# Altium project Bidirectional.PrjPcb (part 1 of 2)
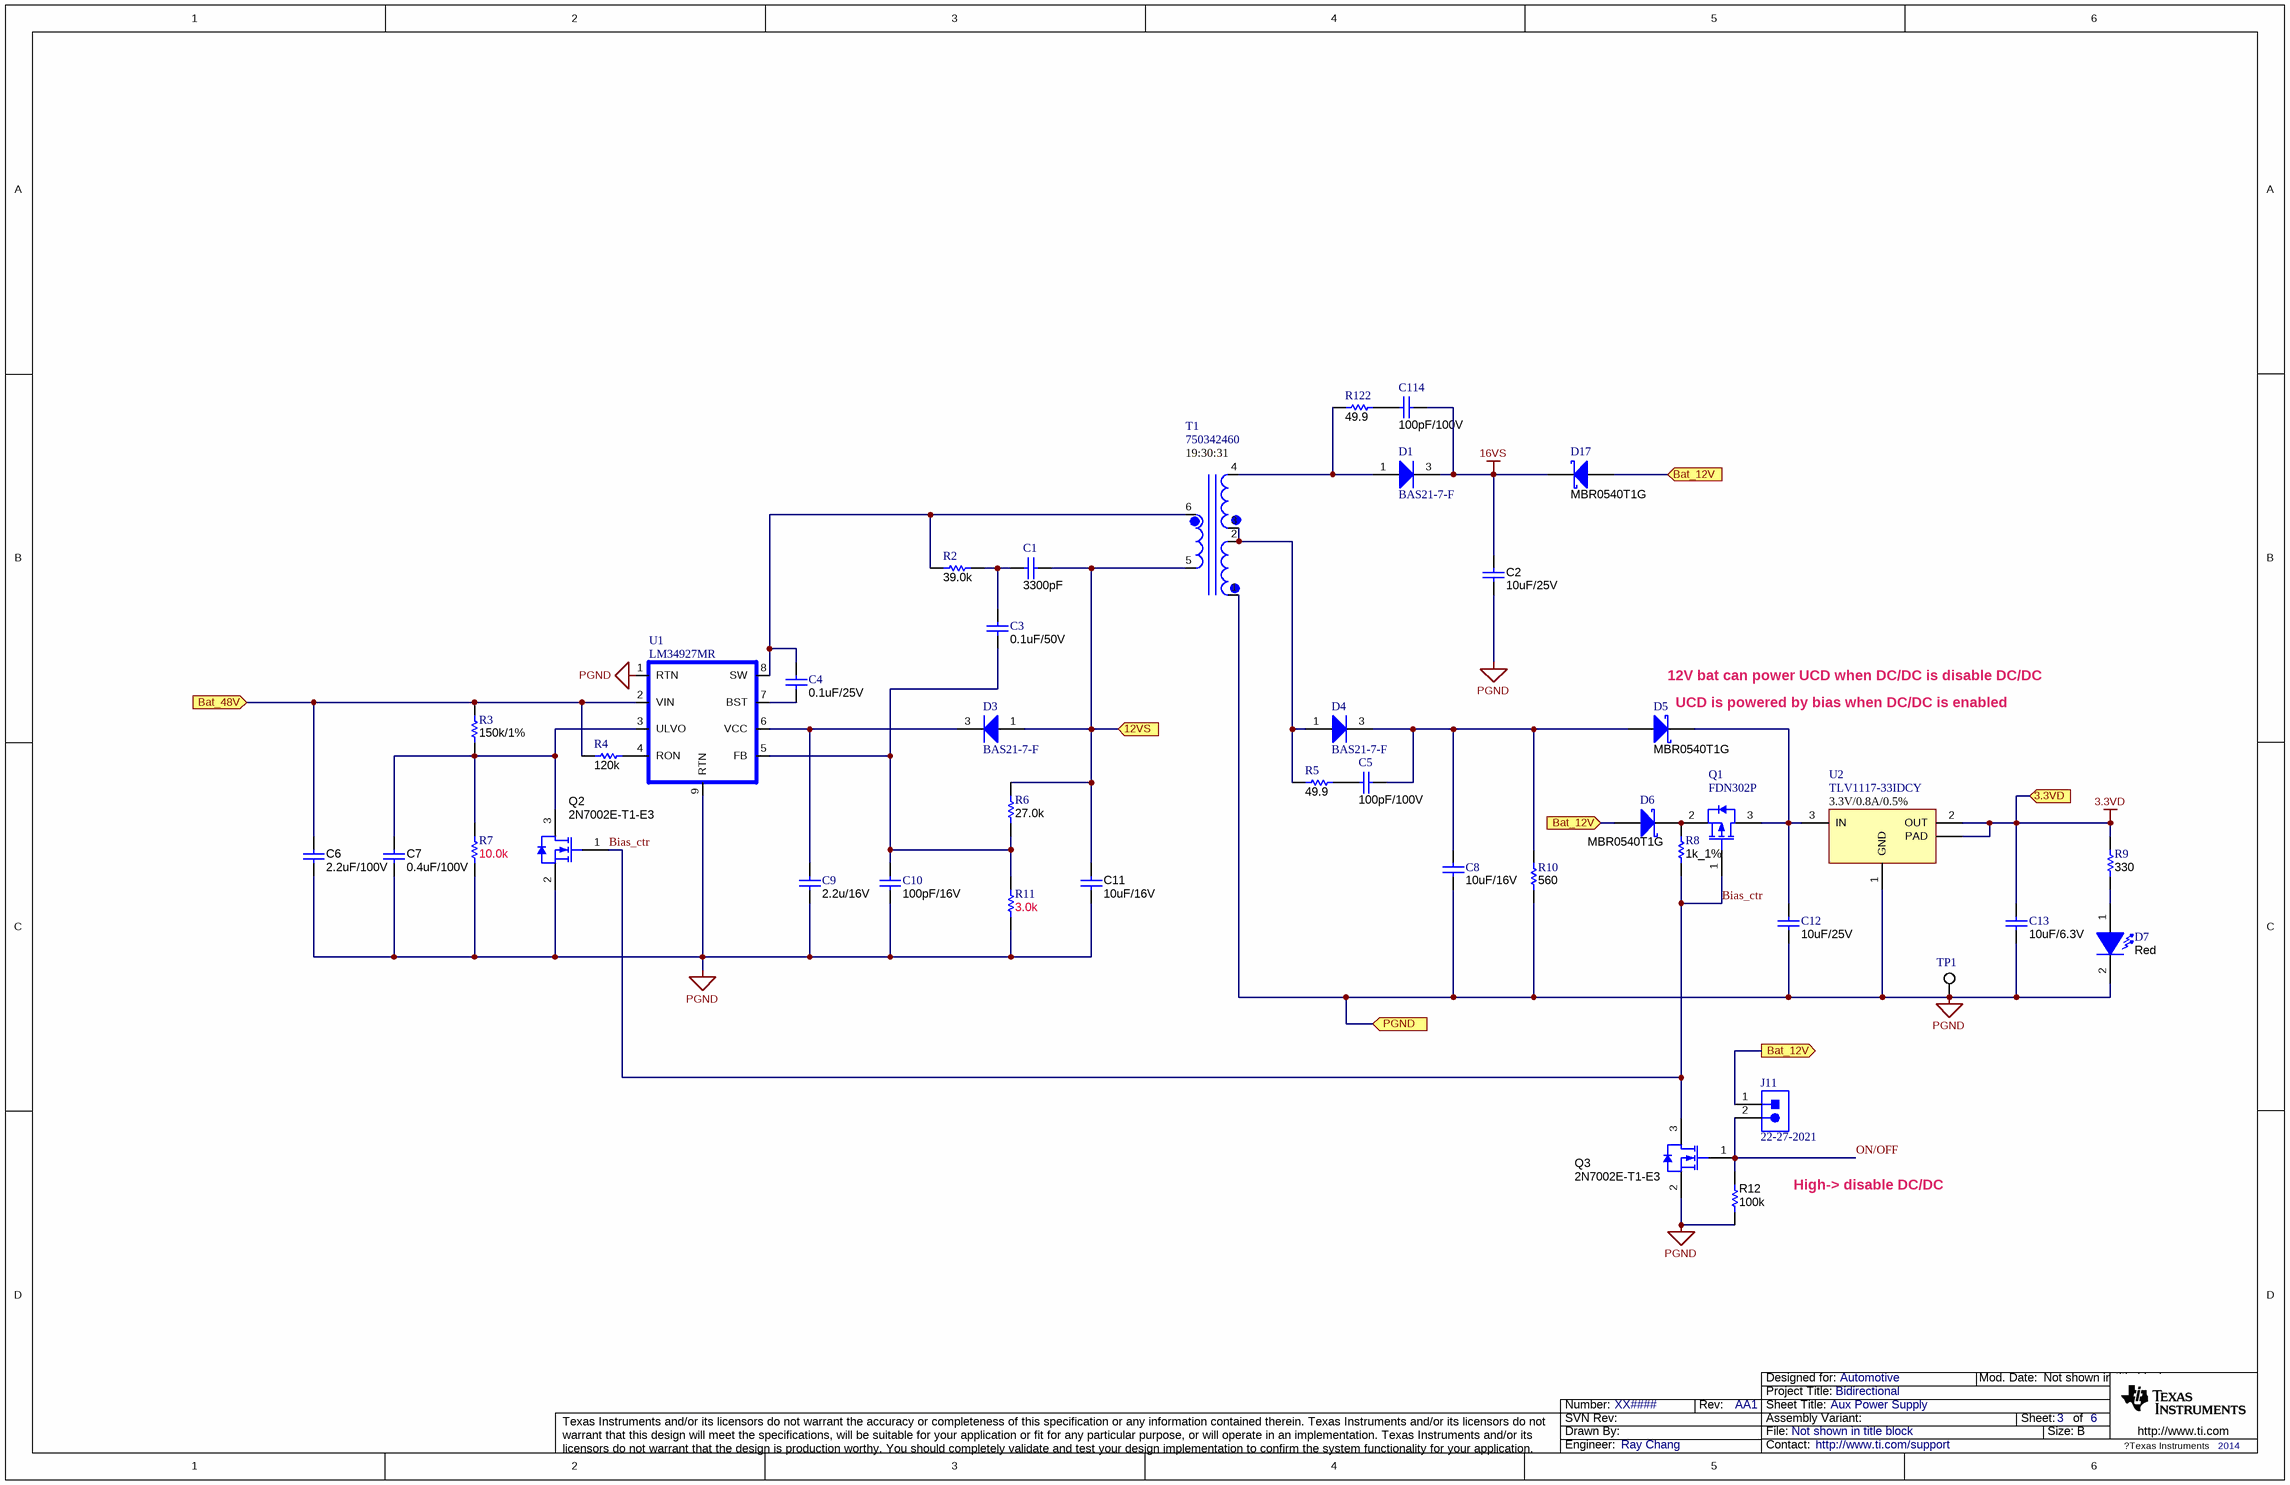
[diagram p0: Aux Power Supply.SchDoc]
CopyrightYear: 2014; PCB_Layout: Ray Chang; PCB_Rev: E1; PRJ_Customer: Automotive; PRJ_Engineer: Ray Chang; PRJ_Number: XX####; PRJ_Title: Bidirectional; SCH_Rev: AA1; TechSupport: http://www.ti.com/support
6 sheets, 417 parts. Net scope: flat (ports and power ports of the same name join across sheets).
Board file: bidirectional.PcbDoc
Sheets:
  Aux Power Supply.SchDoc
  bidirectional-MCU.SchDoc
  bidirectional-phase1.SchDoc
  bidirectional-Phase2&3.SchDoc
  bidirectional-Phase4.SchDoc
  Hardware_ANSI-B.SchDoc

## Sheet Aux Power Supply.SchDoc: Aux Power Supply
size 431 x 279 mm; Date: Not shown in title block; ApprovedBy: Not shown in title block; CheckedBy: Not shown in title block; Author: Not shown in title block; CompanyName: Not shown in title block; Engineer: Not shown in title block; Organization: Not shown in title block; Address1: Not shown in title block; Address2: Not shown in title block; Address3: Not shown in title block; Address4: Not shown in title block; DocumentNumber: 3; Revision: Use project parameter SCH_Rev; SheetNumber: 3; SheetTotal: 6; PageSetup: Record=PageOptions|CenterHorizontal=True|CenterVertical=True|PrintScale=0.96|XCorrection=1.00|YCorrection=1.00|PrintKind=0|BorderSize=5000000|LeftOffset=0|BottomOffset=0|Orientation=2|PaperLength=1000|PaperWidth=1000|Scale=100|PaperSource=15|PrintQuality=600|MediaType=1|DitherType=10|PaperKind=11x17|PrintScaleMode=1

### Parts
C1  ValueDisplayed: 3300pF  [0603]  (hidden comment: 06031C332JAT2A)
C2  ValueDisplayed: 10uF/25V  [0805_HV]  (hidden comment: 0805YD106MAT2A)
C3  ValueDisplayed: 0.1uF/50V  [0603]  (hidden comment: 06035C104KAT2A)
C4  ValueDisplayed: 0.1uF/25V  [0603]  (hidden comment: 06033C104JAT2A)
C5  ValueDisplayed: 100pF/100V  [0603]  (hidden comment: C0603C101J5GAC)
C6  ValueDisplayed: 2.2uF/100V  [1206_190]  (hidden comment: GRM31CR72A225KA73L)
C7  ValueDisplayed: 0.4uF/100V  [1206]  (hidden comment: C3216X7R2A474K)
C8  ValueDisplayed: 10uF/16V  [0805_HV]  (hidden comment: 0805YD106MAT2A)
C9  ValueDisplayed: 2.2u/16V  [0805_HV]  (hidden comment: 0805YD225KAT2A)
C10  ValueDisplayed: 100pF/16V  [0603]  (hidden comment: 06035A101JAT2A)
C11  ValueDisplayed: 10uF/16V  [0805_HV]  (hidden comment: 0805YD106MAT2A)
C12  ValueDisplayed: 10uF/25V  [0805_HV]  (hidden comment: C2012X5R1E106K125AB)
C13  ValueDisplayed: 10uF/6.3V  [0603]  (hidden comment: C0603C106M9PACTU)
C114  ValueDisplayed: 100pF/100V  [0603]  (hidden comment: C0603C101J5GAC)
D1  BAS21-7-F  [SOT-23]
D3  BAS21-7-F  [SOT-23]
D4  BAS21-7-F  [SOT-23]
D5  MBR0540T1G  [SOD-123]
D6  MBR0540T1G  [SOD-123]
D7  value Red  [LED_LTST-C170]  (hidden comment: LTST-C170KRKT)
D17  MBR0540T1G  [SOD-123]
J11  22-27-2021  [MOLEX_22-27-2021]
Q1  FDN302P  [SOT-23]
Q2  2N7002E-T1-E3  [SOT-23]
Q3  2N7002E-T1-E3  [SOT-23]
R2  value 39.0k  [0603]  (hidden comment: RC0603FR-0739KL)
R3  value 150k/1%  [0603]  (hidden comment: CRCW0603150KFKEA)
R4  value 120k  [0603]  (hidden comment: RC0603FR-07120KL)
R5  value 49.9  [0603]  (hidden comment: CRCW060349R9FKEA)
R6  value 27.0k  [0603]  (hidden comment: RC0603FR-0727KL)
R7  value 10.0k  [0603]  (hidden comment: CRCW060310K0FKEA)
R8  value 1k_1%  [0603]  (hidden comment: CRCW06031K00JNEA)
R9  ValueDisplayed: 330  [0603]  (hidden comment: CRCW0603330RJNEA)
R10  value 560  [0603]  (hidden comment: RC0603FR-07560RL)
R11  value 3.0k  [0603]  (hidden comment: CRCW06033K00JNEA)
R12  ValueDisplayed: 100k  [0603]  (hidden comment: CRCW0603100KJNEA)
R122  value 49.9  [0603]  (hidden comment: CRCW060349R9FKEA)
T1  750342460  [XFMR_12X12.5-8P]
TP1  5002  [Keystone5002]  (value not drawn)
U1  LM34927MR  [DDA0008B_M]
U2  TLV1117-33IDCY  [DCY0003A_N]

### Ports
3.3VD, 12VS, Bat_12V, Bat_48V, PGND

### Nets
3.3VD: C13.1 R9.2 U2.2(OUT) U2.4(PAD) ; port 3.3VD
16VS: C2.1 C114.1 D1.3(K) D17.1(K)
PGND: C2.2 C6.2 C7.2 C8.2 C9.2 C10.2 C11.2 C12.2 C13.2 D7.2(K) Q2.2(S) Q3.2(S) R7.1 R10.1 R11.1 R12.1 T1.1 TP1.1 U1.1(RTN) U1.9(RTN) U2.1(GND) ; port PGND
12VS: C1.1 C11.1 D3.1(A) R6.2 T1.5 ; port 12VS
Bat_12V: D6.2(A) D17.2(A) J11.1 ; port Bat_12V
Bat_48V: C6.1 R3.2 R4.1 U1.2(VIN) ; port Bat_48V
Bias_ctr: Q1.1(G) Q2.1(G) Q3.3(D) R8.1
ON/OFF: J11.2 Q3.1(G) R12.2
NetC1_2: C1.2 C3.1 R2.2
NetC3_2: C3.2 C10.1 R6.1 R11.2 U1.5(FB)
NetC4_1: C4.1 R2.1 T1.6 U1.8(SW)
NetC4_2: C4.2 U1.7(BST)
NetC5_1: C5.1 C8.1 D4.3(K) D5.2(A) R10.2
NetC5_2: C5.2 R5.2
NetC7_1: C7.1 Q2.3(D) R3.1 R7.2 U1.3(ULVO)
NetC9_1: C9.1 D3.3(K) U1.6(VCC)
NetC12_1: C12.1 D5.1(K) Q1.3(D) U2.3(IN)
NetC114_2: C114.2 R122.2
NetD1_1: D1.1(A) R122.1 T1.4
NetD4_1: D4.1(A) R5.1 T1.2 T1.3
NetD6_1: D6.1(K) Q1.2(S) R8.2
NetD7_1: D7.1(A) R9.1
NetR4_2: R4.2 U1.4(RON)

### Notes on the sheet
- (near T1) 19:30:31
- (near D5) UCD is powered by bias when DC/DC is enabled
- (near D5) 12V bat can power UCD when DC/DC is disable DC/DC
- (near U2) 3.3V/0.8A/0.5%
- High-> disable DC/DC

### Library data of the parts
C1 = 06031C332JAT2A: CAP, CERM, 3300pF, 100V, +/-5%, X7R, 0603; Manufacturer: AVX; Polarized: N; CompType: Capacitor; U/M: EA; Cap_F: 0.0000000033; Tolerance_%: 5; ESR_Ohm: 0.159; Value1: 0.159 ohm; VDC_V: 100; TaMin_C: -55; TaMax_C: 125
C2 C8 C11 = 0805YD106MAT2A: CAP, CERM, 10uF, 16V, +/-20%, X5R, 0805; Manufacturer: AVX; Polarized: N; CompType: Capacitor; U/M: EA; Cap_F: 0.00001; Tolerance_%: 20; Value1: Unknown; VDC_V: 16; TaMin_C: -55; TaMax_C: 85; Cap_Case: 0805
C3 = 06035C104KAT2A: CAP, CERM, 0.1uF, 50V, +/-10%, X7R, 0603; Manufacturer: AVX; Polarized: N; CompType: Capacitor; U/M: EA; Cap_F: 0.0000001; Tolerance_%: 10; Value1: Unknown; VDC_V: 50; TaMin_C: -55; TaMax_C: 125
C4 = 06033C104JAT2A: CAP, CERM, 0.1uF, 25V, +/-5%, X7R, 0603; Manufacturer: AVX; Polarized: N; CompType: Capacitor; U/M: EA; Cap_F: 0.0000001; Tolerance_%: 5; ESR_Ohm: 0.05; Value1: 0.05 ohm; VDC_V: 25; TaMin_C: -55; TaMax_C: 125
C5 C114 = C0603C101J5GAC: CAP, CERM, 100pF, 50V, +/-5%, C0G/NP0, 0603; Manufacturer: Kemet; Polarized: N; CompType: Capacitor; U/M: EA; Cap_F: 0.0000000001; Tolerance_%: 5; Value1: Unknown; VDC_V: 50; TaMin_C: -55; TaMax_C: 125
C6 = GRM31CR72A225KA73L: CAP, CERM, 2.2uF, 100V, +/-10%, X7R, 1206_190; Manufacturer: MuRata; Polarized: N; CompType: Capacitor; U/M: EA; Cap_F: 0.0000022; Tolerance_%: 10; Value1: Unknown; VDC_V: 100; TaMin_C: -55; TaMax_C: 125
C7 = C3216X7R2A474K: CAP, CERM, 0.47uF, 100V, +/-10%, X7R, 1206; Manufacturer: TDK; Polarized: N; CompType: Capacitor; U/M: EA; Cap_F: 0.00000047; Tolerance_%: 10; ESR_Ohm: 0.0089; Value1: 0.0089 ohm; VDC_V: 100; TaMin_C: -55; TaMax_C: 125
C9 = 0805YD225KAT2A: CAP, CERM, 2.2uF, 16V, +/-10%, X5R, 0805; Manufacturer: AVX; Polarized: N; CompType: Capacitor; U/M: EA; Cap_F: 0.0000022; Tolerance_%: 10; ESR_Ohm: 0.009; Value1: 0.009 ohm; VDC_V: 16; TaMin_C: -55; TaMax_C: 85; Cap_Case: 0805
C10 = 06035A101JAT2A: CAP, CERM, 100pF, 50V, +/-5%, C0G/NP0, 0603; Manufacturer: AVX; Polarized: N; CompType: Capacitor; U/M: EA; Cap_F: 0.0000000001; Tolerance_%: 5; ESR_Ohm: 0.119; Value1: 0.119 ohm; VDC_V: 50; TaMin_C: -55; TaMax_C: 125
C12 = C2012X5R1E106K125AB: CAP, CERM, 10uF, 25V, +/-10%, X5R, 0805; Manufacturer: TDK; Polarized: N; CompType: Capacitor; U/M: EA; Cap_F: 0.00001; Tolerance_%: 10; Value1: Unknown; VDC_V: 25; TaMin_C: -55; TaMax_C: 85; Cap_Case: 0805
C13 = C0603C106M9PACTU: CAP, CERM, 10uF, 6.3V, +/-20%, X5R, 0603; Manufacturer: Kemet; Polarized: N; CompType: Capacitor; U/M: EA; Cap_F: 0.00001; Tolerance_%: 20; ESR_Ohm: 0.004; Value1: 0.004 ohm; VDC_V: 6.3; IRMS_A: 8.9; TaMin_C: -55; TaMax_C: 85
D1 D3 D4 = BAS21-7-F: Diode, Switching, 200V, 0.2A, SOT-23; Manufacturer: Diodes Inc.; U/M: EA; Vf_V: 1.25; Value2: 1.25V; Io_A: 0.2; Vr_V: 200; TJmax_C: 150; RJC_CperW: 500
D5 D6 = MBR0540T1G: Diode, Schottky, 40 V, 0.5 A, SOD-123; Manufacturer: ON Semiconductor; Value: 40V; U/M: EA; Vf_V: 0.51; Value1: 0.5A; Value2: 0.51V; Io_A: 0.5; Vr_V: 40; TJmax_C: 150; RJC_CperW: 118; AEC Category: Q101
D7 = LTST-C170KRKT: LED, Red, SMD; Manufacturer: Lite-On; Type: AlInGaP; Vf_V: 2; Value2: 2V; Io_A: 0.02; Value1: W; U/M: EA
D17 = MBR0540T1G: Diode, Schottky, 40 V, 0.5 A, SOD-123; Manufacturer: ON Semiconductor; Value: 40V; U/M: EA; Vf_V: 0.51; Value1: 0.5A; Value2: 0.51V; Io_A: 0.5; Vr_V: 40; TJmax_C: 150; RJC_CperW: 118
J11 = 22-27-2021: Header,2x1, 100mil, TH; Manufacturer: Molex; SymbolCreator: a0412235; U/M: EA
Q1 = FDN302P: MOSFET, P-CH, -20V, -2.4A, SOT-23; Manufacturer: Fairchild Semiconductor; Alternate Manufacturer: None; U/M: EA; ChType: P; VdsMax_V: -20; Value1: 0.055 ohm; Rdson45_Ohm: 0.055; Value2: 9 nC; QgTyp_nC: 9; Vgs_V: 12; IdsMax_A: -2.4
Q2 Q3 = 2N7002E-T1-E3: MOSFET, N-CH, 60V, 0.24A, SOT-23; Manufacturer: Vishay-Siliconix; Alternate Manufacturer: None; U/M: EA; ChType: N; VdsMax_V: 60; Value1: 1.8 ohm; Rdson45_Ohm: 1.8; Value2: 0.4 nC; QgTyp_nC: 0.4; Vgs_V: 20; IdsMax_A: 0.24
R2 = RC0603FR-0739KL: RES, 39.0k ohm, 1%, 0.1W, 0603; Manufacturer: Yageo America; CompType: Resistor; Res_ohm: 39000; Value_Code: 39k0; Tolerance_%: 1; Power_W: 0.1; VDC_V: 150; TempCo: 200 ppm/C; U/M: EA
R3 = CRCW0603150KFKEA: RES, 150k ohm, 1%, 0.1W, 0603; Manufacturer: Vishay-Dale; CompType: Resistor; Res_ohm: 150000; Tolerance_%: 1; Power_W: 0.1; VDC_V: 75; TempCo: 100 ppm/C; EIA_Code: E96; U/M: EA
R4 = RC0603FR-07120KL: RES, 120k ohm, 1%, 0.1W, 0603; Manufacturer: Yageo America; CompType: Resistor; Res_ohm: 120000; Tolerance_%: 1; Power_W: 0.1; VDC_V: 150; TempCo: 200 ppm/C; U/M: EA
R5 R122 = CRCW060349R9FKEA: RES, 49.9 ohm, 1%, 0.1W, 0603; Manufacturer: Vishay-Dale; CompType: Resistor; Value_Code: 49R9; Tolerance_%: 1; Power_W: 0.1; VDC_V: 75; TempCo: 100 ppm/C; EIA_Code: E96; U/M: EA
R6 = RC0603FR-0727KL: RES, 27.0k ohm, 1%, 0.1W, 0603; Manufacturer: Yageo America; CompType: Resistor; Res_ohm: 27000; Value_Code: 27k0; Tolerance_%: 1; Power_W: 0.1; VDC_V: 150; TempCo: 200 ppm/C; U/M: EA
R7 = CRCW060310K0FKEA: RES, 10.0k ohm, 1%, 0.1W, 0603; Manufacturer: Vishay-Dale; CompType: Resistor; Res_ohm: 10000; Value_Code: 10k0; Tolerance_%: 1; Power_W: 0.1; VDC_V: 75; TempCo: 100 ppm/C; EIA_Code: E96; U/M: EA
R8 = CRCW06031K00JNEA: RES, 1.0k ohm, 5%, 0.1W, 0603; Manufacturer: Vishay-Dale; CompType: Resistor; Res_ohm: 1000; Value_Code: 1k00; Tolerance_%: 5; Power_W: 0.1; VDC_V: 75; TempCo: 200 ppm/C; EIA_Code: E24; U/M: EA
R9 = CRCW0603330RJNEA: RES, 330, 5%, 0.1 W, 0603; Manufacturer: Vishay-Dale; CompType: Resistor; Value: 330; Value_Code: 330R; Tolerance_%: 5; Power_W: 0.1; Value2: 0.1W; VDC_V: 75; TempCo: 200 ppm/C; EIA_Code: E24; U/M: EA
R10 = RC0603FR-07560RL: RES, 560 ohm, 1%, 0.1W, 0603; Manufacturer: Yageo America; CompType: Resistor; Value_Code: 560R; Tolerance_%: 1; Power_W: 0.1; VDC_V: 150; TempCo: 200 ppm/C; U/M: EA
R11 = CRCW06033K00JNEA: RES, 3.0k ohm, 5%, 0.1W, 0603; Manufacturer: Vishay-Dale; CompType: Resistor; Res_ohm: 3000; Value_Code: 3k00; Tolerance_%: 5; Power_W: 0.1; VDC_V: 75; TempCo: 200 ppm/C; EIA_Code: E24; U/M: EA
R12 = CRCW0603100KJNEA: RES, 100 k, 5%, 0.1 W, 0603; Manufacturer: Vishay-Dale; CompType: Resistor; Value: 100k; Res_ohm: 100000; Tolerance_%: 5; Power_W: 0.1; Value2: 0.1W; VDC_V: 75; TempCo: 200 ppm/C; EIA_Code: E24; U/M: EA
T1 = XFMR_BSEPC10-138: xfmr, ?0%; Manufacturer: WURTH ELEKTRONIK; Area: 187.2 mm; Value: 60 uH
TP1 = 5002: Test Point, Miniature, White, TH; Manufacturer: Keystone; CompType: Test Point Loop; U/M: EA
U1 = LM34927MR: IC, Integrated Secondary Side Bias Regulator; Manufacturer: TI; Alternate Manufacturer: None; Area: 75900
U2 = TLV1117-33IDCY: FIXED LOW-DROPOUT VOLTAGE REGULATOR, DCY0003A; Alternate Manufacturer: None; Manufacturer: Texas Instruments; SymbolCreator: a0411947; CompType: IC; U/M: EA

## Sheet bidirectional-MCU.SchDoc: MCU
size 431 x 279 mm; Date: Not shown in title block; ApprovedBy: Not shown in title block; CheckedBy: Not shown in title block; Author: Not shown in title block; CompanyName: Not shown in title block; Engineer: Not shown in title block; Organization: Not shown in title block; Address1: Not shown in title block; Address2: Not shown in title block; Address3: Not shown in title block; Address4: Not shown in title block; DocumentNumber: 1; Revision: Use project parameter SCH_Rev; SheetNumber: 1; SheetTotal: 6; PageSetup: Record=PageOptions|CenterHorizontal=True|CenterVertical=True|PrintScale=0.96|XCorrection=1.00|YCorrection=1.00|PrintKind=0|BorderSize=5000000|LeftOffset=0|BottomOffset=0|Orientation=2|PaperLength=1000|PaperWidth=1000|Scale=100|PaperSource=15|PrintQuality=600|MediaType=1|DitherType=10|PaperKind=11x17|PrintScaleMode=1
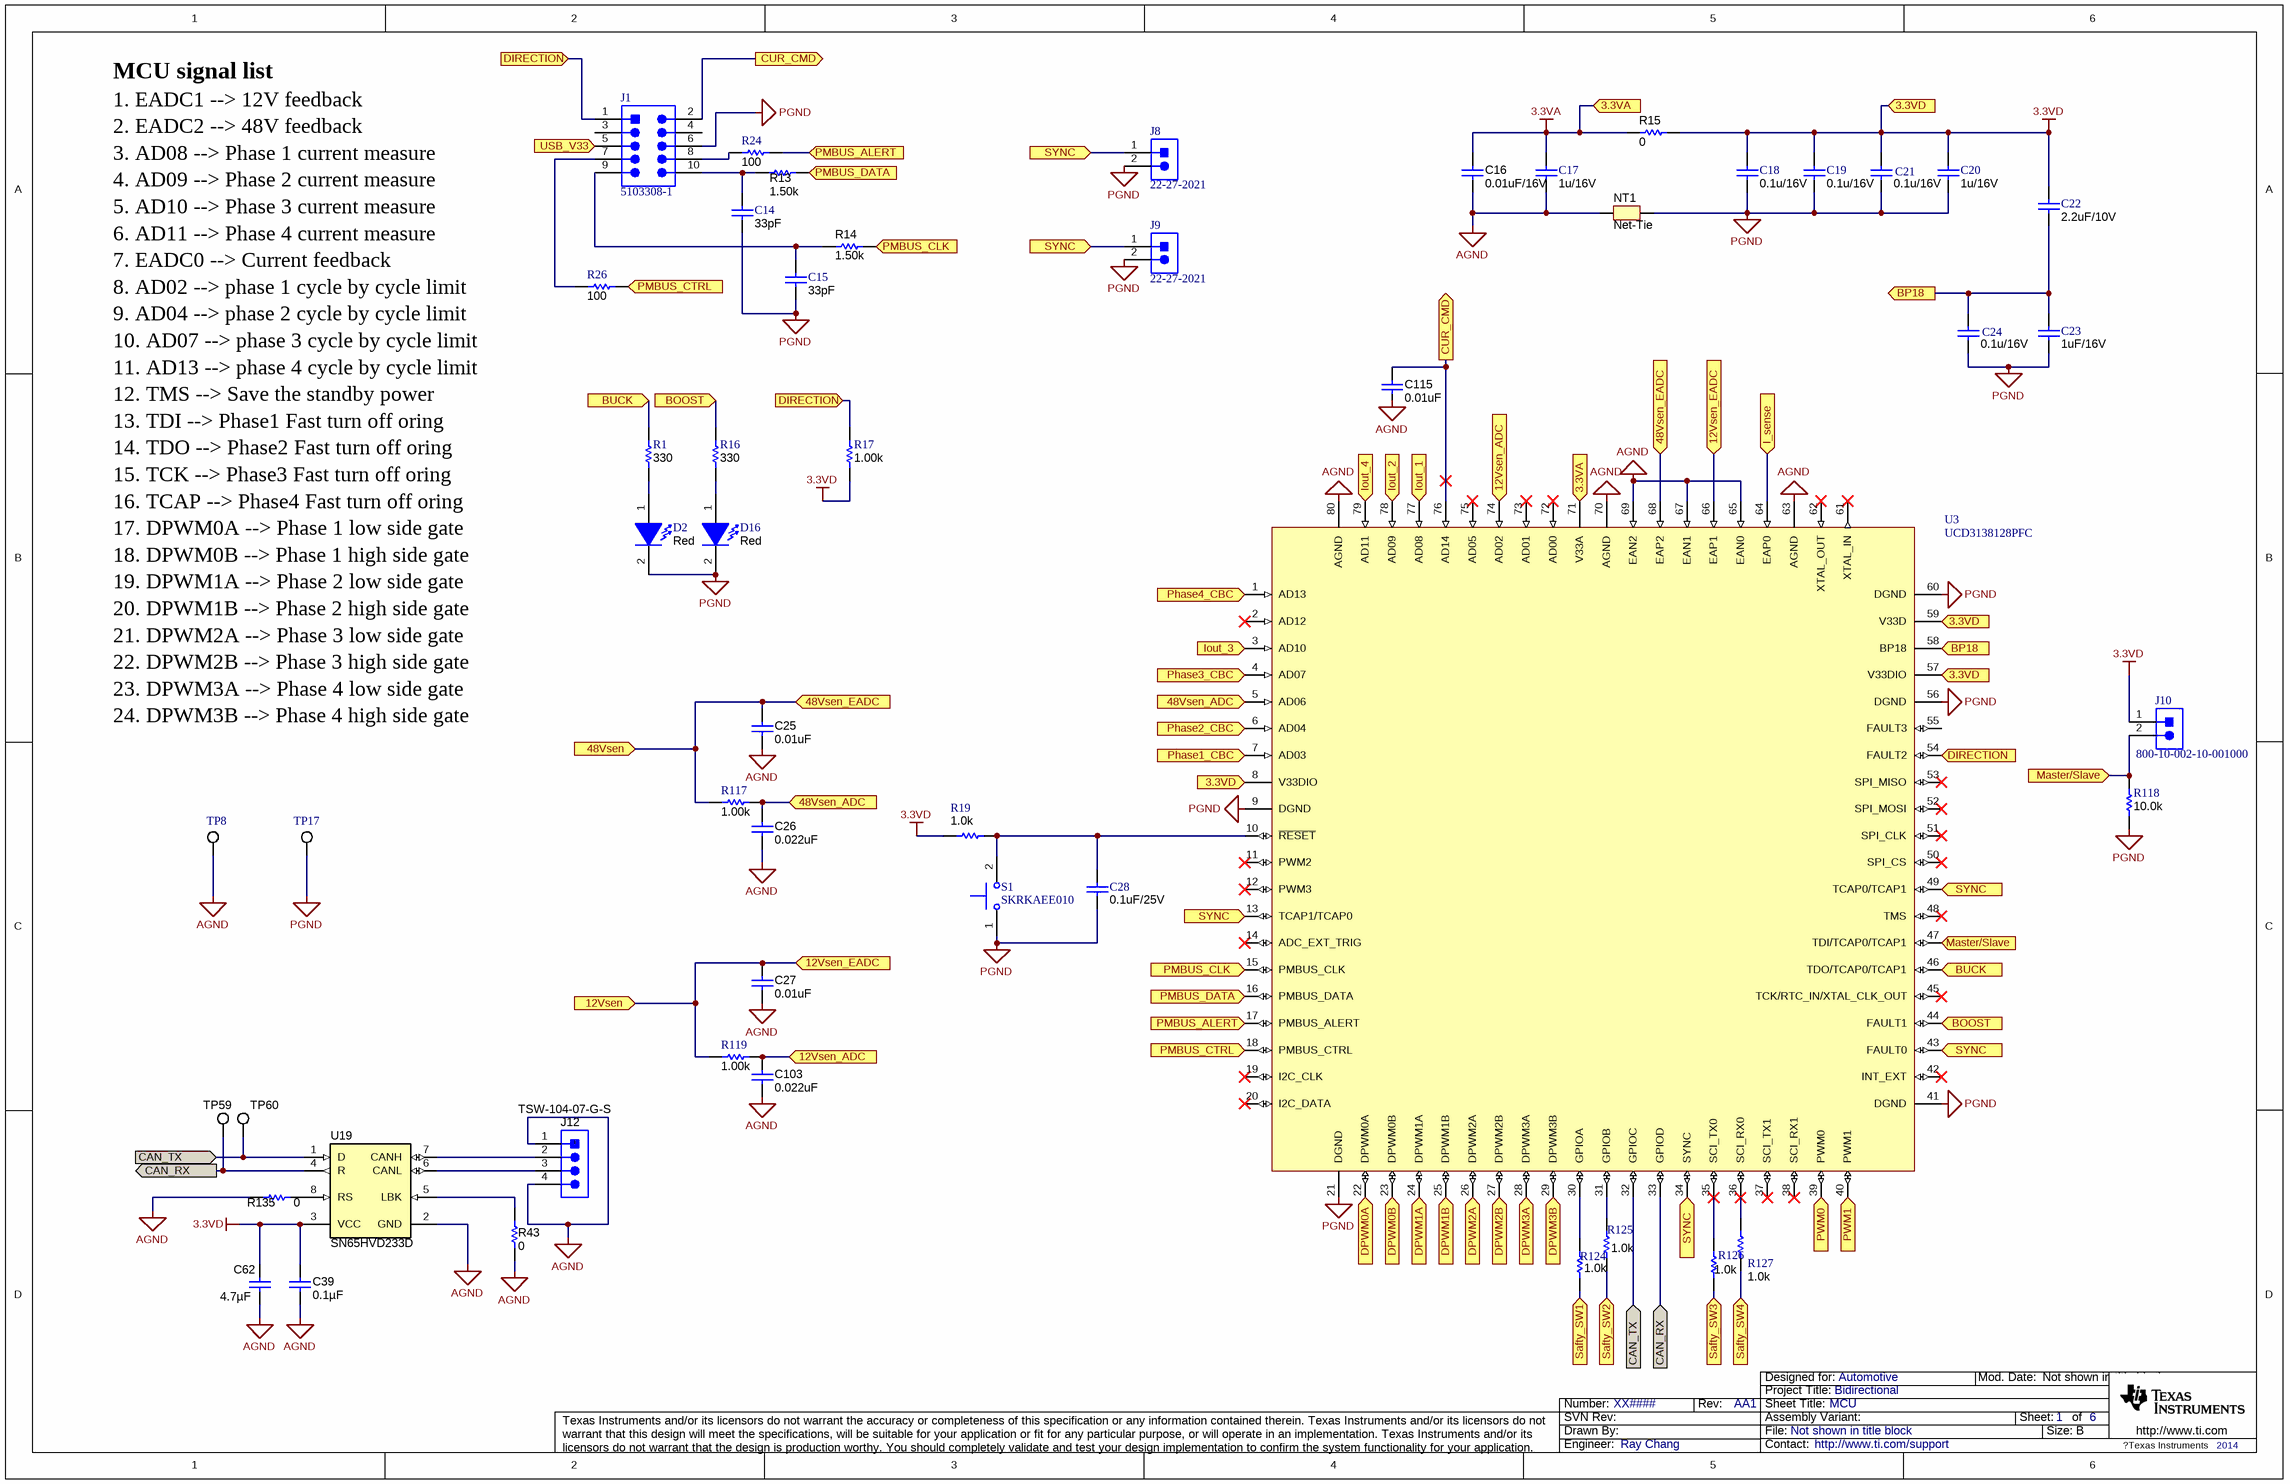
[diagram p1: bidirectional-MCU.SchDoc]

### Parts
(Parts that share a designator on the sheet are numbered #1, #2 ... from top to bottom, then left to right.)
C14  ValueDisplayed: 33pF  [0603]  (hidden comment: 06031A330JAT2A)
C15  ValueDisplayed: 33pF  [0603]  (hidden comment: 06031A330JAT2A)
C16  ValueDisplayed: 0.01uF/16V  [0603]  (hidden comment: 06031C103JAT2A)
C17  ValueDisplayed: 1u/16V  [0603]  (hidden comment: C0603C105K4PACTU)
C18  ValueDisplayed: 0.1u/16V  [0603]  (hidden comment: 0603YC104JAT2A)
C19  ValueDisplayed: 0.1u/16V  [0603]  (hidden comment: 0603YC104JAT2A)
C20  ValueDisplayed: 1u/16V  [0603]  (hidden comment: C0603C105K4PACTU)
C21  ValueDisplayed: 0.1u/16V  [0603]  (hidden comment: 0603YC104JAT2A)
C22  ValueDisplayed: 2.2uF/10V  [0603]  (hidden comment: C0603C225K8PACTU)
C23  ValueDisplayed: 1uF/16V  [0603]  (hidden comment: C0603C105K4PACTU)
C24  ValueDisplayed: 0.1u/16V  [0603]  (hidden comment: 0603YC104JAT2A)
C25  ValueDisplayed: 0.01uF  [0603]  (hidden comment: 06031C103JAT2A)
C26  ValueDisplayed: 0.022uF  [0603]  (hidden comment: C0603C223K3RACTU)
C27  ValueDisplayed: 0.01uF  [0603]  (hidden comment: 06031C103JAT2A)
C28  ValueDisplayed: 0.1uF/25V  [0603]  (hidden comment: 06033C104JAT2A)
C39#1  ValueDisplayed: 0.1µF  [0603]  (hidden comment: GRM188R71E104KA01D)
C62  ValueDisplayed: 4.7µF  [0805_HV]  (hidden comment: C2012X5R1E475K125AB)
C103  ValueDisplayed: 0.022uF  [0603]  (hidden comment: C0603C223K3RACTU)
C115  ValueDisplayed: 0.01uF  [0603]  (hidden comment: 06031C103JAT2A)
D2  value Red  [LED_LTST-C170]  (hidden comment: LTST-C170KRKT)
D16  value Red  [LED_LTST-C170]  (hidden comment: LTST-C170KRKT)
J1  5103308-1  [CONN_5103308-1]
J8  22-27-2021  [MOLEX_22-27-2021]
J9  22-27-2021  [MOLEX_22-27-2021]
J10  800-10-002-10-001000  [Mill-Max_800-10-002-10-001000]
J12  TSW-104-07-G-S  [TSW-104-07-G-S]
NT1  Net-Tie  [Net-Tie_10mil]  (net tie, no BOM)
R1  value 330  [0603]  (hidden comment: RC0603FR-07330RL)
R13  value 1.50k  [0603]  (hidden comment: RG1608P-152-B-T5)
R14  value 1.50k  [0603]  (hidden comment: RG1608P-152-B-T5)
R15  value 0  [0603]  (hidden comment: MCR03EZPJ000)
R16  value 330  [0603]  (hidden comment: RC0603FR-07330RL)
R17  value 1.00k  [0603]  (hidden comment: CRCW06031K00FKEA)
R19  value 1.0k  [0603]  (hidden comment: CRCW06031K00JNEA)
R24  value 100  [0603]  (hidden comment: CRCW0603100RFKEA)
R26  value 100  [0603]  (hidden comment: CRCW0603100RFKEA)
R43#1  value 0  [0805_HV]  (hidden comment: CRCW08050000Z0EA)
R117  value 1.00k  [0603]  (hidden comment: CRCW06031K00FKEA)
R118  value 10.0k  [0603]  (hidden comment: CRCW060310K0FKEA)
R119  value 1.00k  [0603]  (hidden comment: CRCW06031K00FKEA)
R124  value 1.0k  [0603L]  (hidden comment: CRCW06031K00JNEA)
R125  value 1.0k  [0603]  (hidden comment: CRCW06031K00JNEA)
R126  value 1.0k  [0603]  (hidden comment: CRCW06031K00JNEA)
R127  value 1.0k  [0603]  (hidden comment: CRCW06031K00JNEA)
R135  value 0  [0805_HV]  (hidden comment: CRCW08050000Z0EA)
S1  SKRKAEE010  [SW_SKRKAEE010]
TP8  5002  [Keystone5002]  (value not drawn)
TP17  5002  [Keystone5002]  (value not drawn)
TP59  5002  [Keystone5002]  (value not drawn)
TP60  5002  [Keystone5002]  (value not drawn)
U3  UCD3138128PFC  [PFC0080A_N]
U19  SN65HVD233D  [D0008A_L]

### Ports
3.3VA, 3.3VD, 12Vsen, 12Vsen_ADC, 12Vsen_EADC, 48Vsen, 48Vsen_ADC, 48Vsen_EADC, BOOST, BP18, BUCK, CAN_RX, CAN_TX, CAN_TX (in), CUR_CMD, DIRECTION, DPWM0A, DPWM0B, DPWM1A, DPWM1B, DPWM2A, DPWM2B, DPWM3A, DPWM3B, I_sense, Iout_1, Iout_2, Iout_3, Iout_4, Master/Slave, Phase1_CBC, Phase2_CBC, Phase3_CBC, Phase4_CBC, PMBUS_ALERT, PMBUS_CLK, PMBUS_CTRL, PMBUS_DATA, PWM0, PWM1, Safty_SW1, Safty_SW2, Safty_SW3, Safty_SW4, SYNC, USB_V33

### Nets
3.3VA: C16.1 C17.1 R15.1 U3.71(V33A) ; port 3.3VA
3.3VD: C18.1 C19.1 C20.1 C21.1 C22.2 C39#1.1 C62.1 J10.1 R15.2 R17.1 R19.1 U3.8(V33DIO) U3.57(V33DIO) U3.59(V33D) U19.3(VCC) ; port 3.3VD
AGND: C16.2 C17.2 C25.2 C26.2 C27.2 C39#1.2 C62.2 C103.2 J12.1 J12.4 NT1.1 R43#1.1 R135.2 TP8.1 U3.63(AGND) U3.65(EAN0) U3.67(EAN1) U3.69(EAN2) U3.70(AGND) U3.80(AGND) U19.2(GND)
PGND: C14.2 C15.2 C18.2 C19.2 C20.2 C21.2 C23.2 C24.2 C28.2 D2.2(K) D16.2(K) J1.6 J8.2 J9.2 NT1.2 R118.1 S1.1 TP17.1 U3.9(DGND) U3.21(DGND) U3.41(DGND) U3.56(DGND) U3.60(DGND)
12Vsen: C27.1 R119.1 U3.66(EAP1) ; port 12Vsen_EADC, port 12Vsen
12Vsen_ADC: C103.1 R119.2 U3.74(AD02) ; port 12Vsen_ADC
48Vsen: C25.1 R117.1 U3.68(EAP2) ; port 48Vsen_EADC, port 48Vsen
48Vsen_ADC: C26.1 R117.2 U3.5(AD06) ; port 48Vsen_ADC
BOOST: R16.2 U3.44(FAULT1) ; port BOOST
BP18: C22.1 C23.1 C24.1 U3.58(BP18) ; port BP18
BUCK: R1.2 U3.46(TDO/TCAP0/TCAP1) ; port BUCK
CAN_RX: TP59.1 U3.33(GPIOD) U19.4(R) ; port CAN_RX
CAN_TX: TP60.1 U3.32(GPIOC) U19.1(D) ; port CAN_TX
CUR_CMD: C115.1 J1.2 U3.76(AD14) ; port CUR_CMD
DIRECTION: J1.1 R17.2 U3.54(FAULT2) ; port DIRECTION
DPWM0A: U3.22(DPWM0A) ; port DPWM0A
DPWM0B: U3.23(DPWM0B) ; port DPWM0B
DPWM1A: U3.24(DPWM1A) ; port DPWM1A
DPWM1B: U3.25(DPWM1B) ; port DPWM1B
DPWM2A: U3.26(DPWM2A) ; port DPWM2A
DPWM2B: U3.27(DPWM2B) ; port DPWM2B
DPWM3A: U3.28(DPWM3A) ; port DPWM3A
DPWM3B: U3.29(DPWM3B) ; port DPWM3B
I_sense: U3.64(EAP0) ; port I_sense
Iout_1: U3.77(AD08) ; port Iout_1
Iout_2: U3.78(AD09) ; port Iout_2
Iout_3: U3.3(AD10) ; port Iout_3
Iout_4: U3.79(AD11) ; port Iout_4
Master/Slave: J10.2 R118.2 U3.47(TDI/TCAP0/TCAP1) ; port Master/Slave
Phase1_CBC: U3.7(AD03) ; port Phase1_CBC
Phase2_CBC: U3.6(AD04) ; port Phase2_CBC
Phase3_CBC: U3.4(AD07) ; port Phase3_CBC
Phase4_CBC: U3.1(AD13) ; port Phase4_CBC
PMBUS_ALERT: R24.2 U3.17(PMBUS_ALERT) ; port PMBUS_ALERT
PMBUS_CLK: R14.2 U3.15(PMBUS_CLK) ; port PMBUS_CLK
PMBUS_CTRL: R26.2 U3.18(PMBUS_CTRL) ; port PMBUS_CTRL
PMBUS_DATA: R13.2 U3.16(PMBUS_DATA) ; port PMBUS_DATA
PWM0: U3.39(PWM0) ; port PWM0
PWM1: U3.40(PWM1) ; port PWM1
Safty_SW1: R124.1 ; port Safty_SW1
Safty_SW2: R125.1 ; port Safty_SW2
Safty_SW3: R126.1 ; port Safty_SW3
Safty_SW4: R127.1 ; port Safty_SW4
SYNC: J8.1 J9.1 U3.13(TCAP1/TCAP0) U3.34(SYNC) U3.43(FAULT0) U3.49(TCAP0/TCAP1) ; port SYNC
USB_V33: J1.5 ; port USB_V33
NetC14_1: C14.1 J1.10 R13.1
NetC15_1: C15.1 J1.9 R14.1
NetC28_1: C28.1 R19.2 S1.2 U3.10(~{RESET})
NetD2_1: D2.1(A) R1.1
NetD16_1: D16.1(A) R16.1
NetJ1_7: J1.7 R26.1
NetJ1_8: J1.8 R24.1
NetJ12_2: J12.2 U19.7(CANH)
NetJ12_3: J12.3 U19.6(CANL)
NetR43#1_2: R43#1.2 U19.5(LBK)
NetR124_2: R124.2 U3.30(GPIOA)
NetR125_2: R125.2 U3.31(GPIOB)
NetR126_2: R126.2 U3.35(SCI_TX0)
NetR127_2: R127.2 U3.36(SCI_RX0)
NetR135_1: R135.1 U19.8(RS)

Not connected (* = marked no-connect by the designer): C115 2; J1 3 4; U3 2(AD12)* 11(PWM2)* 12(PWM3)* 14(ADC_EXT_TRIG)* 19(I2C_CLK)* 20(I2C_DATA)* 37(SCI_TX1)* 38(SCI_RX1)* 42(INT_EXT)* 45(TCK/RTC_IN/XTAL_CLK_OUT)* 48(TMS)* 50(SPI_CS)* 51(SPI_CLK)* 52(SPI_MOSI)* 53(SPI_MISO)* 55(FAULT3) 61(XTAL_IN)* 62(XTAL_OUT)* 72(AD00)* 73(AD01)* 75(AD05)*

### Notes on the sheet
- MCU signal list
- 1. EADC1 --> 12V feedback
- 2. EADC2 --> 48V feedback
- 3. AD08 --> Phase 1 current measure
- 4. AD09 --> Phase 2 current measure
- 5. AD10 --> Phase 3 current measure
- 7. EADC0 --> Current feedback
- (near R26) 8. AD02 --> phase 1 cycle by cycle limit
- 6. AD11 --> Phase 4 current measure
- (near R26) 9. AD04 --> phase 2 cycle by cycle limit
- (near R26) 10. AD07 --> phase 3 cycle by cycle limit
- 12. TMS --> Save the standby power
- 13. TDI --> Phase1 Fast turn off oring
- 11. AD13 --> phase 4 cycle by cycle limit
- 14. TDO --> Phase2 Fast turn off oring
- 15. TCK --> Phase3 Fast turn off oring
- 17. DPWM0A --> Phase 1 low side gate
- 18. DPWM0B --> Phase 1 high side gate
- 16. TCAP --> Phase4 Fast turn off oring
- 19. DPWM1A --> Phase 2 low side gate
- 20. DPWM1B --> Phase 2 high side gate
- 21. DPWM2A --> Phase 3 low side gate
- 22. DPWM2B --> Phase 3 high side gate
- 23. DPWM3A --> Phase 4 low side gate
- 24. DPWM3B --> Phase 4 high side gate
- Labels drawn without touching a wire or pin: AGND

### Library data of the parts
C14 C15 = 06031A330JAT2A: CAP, CERM, 33pF, 100V, +/-5%, C0G/NP0, 0603; Manufacturer: AVX; Polarized: N; CompType: Capacitor; U/M: EA; Cap_F: 0.000000000033; Tolerance_%: 5; ESR_Ohm: 0.209; Value1: 0.209 ohm; VDC_V: 100; TaMin_C: -55; TaMax_C: 125
C16 C25 C27 C115 = 06031C103JAT2A: CAP, CERM, 0.01uF, 100V, +/-5%, X7R, 0603; Manufacturer: AVX; Polarized: N; CompType: Capacitor; U/M: EA; Cap_F: 0.00000001; Tolerance_%: 5; ESR_Ohm: 0.098; Value1: 0.098 ohm; VDC_V: 100; TaMin_C: -55; TaMax_C: 125
C17 C20 C23 = C0603C105K4PACTU: CAP, CERM, 1uF, 16V, +/-10%, X5R, 0603; Manufacturer: Kemet; Polarized: N; CompType: Capacitor; U/M: EA; Cap_F: 0.000001; Tolerance_%: 10; Value1: Unknown; VDC_V: 16; TaMin_C: -55; TaMax_C: 85
C18 C19 C21 C24 = 0603YC104JAT2A: CAP, CERM, 0.1uF, 16V, +/-5%, X7R, 0603; Manufacturer: AVX; Polarized: N; CompType: Capacitor; U/M: EA; Cap_F: 0.0000001; Tolerance_%: 5; ESR_Ohm: 0.039; Value1: 0.039 ohm; VDC_V: 16; TaMin_C: -55; TaMax_C: 125
C22 = C0603C225K8PACTU: CAP, CERM, 2.2uF, 10V, +/-10%, X5R, 0603; Manufacturer: Kemet; Polarized: N; CompType: Capacitor; U/M: EA; Cap_F: 0.0000022; Tolerance_%: 10; Value1: Unknown; TaMin_C: -55; TaMax_C: 85
C26 C103 = C0603C223K3RACTU: CAP, CERM, 0.022uF, 25V, +/-10%, X7R, 0603; Manufacturer: Kemet; Polarized: N; CompType: Capacitor; U/M: EA; Cap_F: 0.000000022; Tolerance_%: 10; Value1: Unknown; VDC_V: 25; TaMin_C: -55; TaMax_C: 125
C28 = 06033C104JAT2A: as C4 on sheet Aux Power Supply
C39#1 = GRM188R71E104KA01D: CAP, CERM, 0.1uF, 25V, +/-10%, X7R, 0603; Manufacturer: MuRata; Polarized: N; CompType: Capacitor; U/M: EA; Cap_F: 0.0000001; Tolerance_%: 10; Value1: Unknown; VDC_V: 25; TaMin_C: -55; TaMax_C: 125
C62 = C2012X5R1E475K125AB: CAP, CERM, 4.7uF, 25V, +/-10%, X5R, 0805; Manufacturer: TDK; Polarized: N; CompType: Capacitor; U/M: EA; Cap_F: 0.0000047; Tolerance_%: 10; Value1: Unknown; VDC_V: 25; TaMin_C: -55; TaMax_C: 85; Cap_Case: 0805
D2 D16 = LTST-C170KRKT: as D7 on sheet Aux Power Supply
J1 = 5103308-1: Header (shrouded), 100mil, 5x2, Gold, TH; Manufacturer: TE Connectivity; SymbolCreator: a0412235; CompType: Connector; U/M: EA
J8 J9 = 22-27-2021: as J11 on sheet Aux Power Supply
J10 = 800-10-002-10-001000: Header, 2x1, 100mil, SMT; Manufacturer: Mill-Max; SymbolCreator: a0412235; U/M: EA
J12 = TSW-104-07-G-S: Header, TH, 100mil, 4x1, Gold plated, 230 mil above insulator; Manufacturer: Samtec; SymbolCreator: a0412235; U/M: EA
NT1 = Net-Tie: Single point connection between nets.; SymbolCreator: codlsc
R1 R16 = RC0603FR-07330RL: RES, 330 ohm, 1%, 0.1W, 0603; Manufacturer: Yageo America; CompType: Resistor; Value_Code: 330R; Tolerance_%: 1; Power_W: 0.1; VDC_V: 150; TempCo: 200 ppm/C; U/M: EA
R13 R14 = RG1608P-152-B-T5: RES, 1.50k ohm, 0.1%, 0.1W, 0603; Manufacturer: Susumu Co Ltd; CompType: Resistor; Res_ohm: 1500; Value_Code: 1k50; Tolerance_%: 0.1; VDC_V: 75; TempCo: 25 ppm/C; EIA_Code: E192; U/M: EA
R15 = MCR03EZPJ000: RES, 0 ohm, 5%, 0.1W, 0603; Manufacturer: Rohm; CompType: Resistor; Value_Code: 0000; Tolerance_%: 5; Power_W: 0.1; VDC_V: 50; TempCo: 400 ppm/C; EIA_Code: E24; U/M: EA
R17 R117 R119 = CRCW06031K00FKEA: RES, 1.00k ohm, 1%, 0.1W, 0603; Manufacturer: Vishay-Dale; CompType: Resistor; Res_ohm: 1000; Value_Code: 1k00; Tolerance_%: 1; Power_W: 0.1; VDC_V: 75; TempCo: 100 ppm/C; EIA_Code: E96; U/M: EA
R19 R124-R127 = CRCW06031K00JNEA: as R8 on sheet Aux Power Supply
R24 R26 = CRCW0603100RFKEA: RES, 100 ohm, 1%, 0.1W, 0603; Manufacturer: Vishay-Dale; CompType: Resistor; Value_Code: 100R; Tolerance_%: 1; Power_W: 0.1; VDC_V: 75; TempCo: 100 ppm/C; EIA_Code: E96; U/M: EA
R43#1 R135 = CRCW08050000Z0EA: RES, 0 ohm, 5%, 0.125W, 0805; Manufacturer: Vishay-Dale; CompType: Resistor; Value_Code: 0000; Tolerance_%: 5; Power_W: 0.125; VDC_V: 150; TempCo: 200 ppm/C; EIA_Code: E24; U/M: EA
R118 = CRCW060310K0FKEA: as R7 on sheet Aux Power Supply
S1 = SKRKAEE010: Switch, Push Button, SMD; Manufacturer: Alps; SymbolCreator: a0412235; Circuit: SPST-NO; VDC_V: 12; SwitchFunction: Off-Mom; PositionCount: 1; CurrentRating_mA: 50
TP8 TP17 TP59 TP60 = 5002: as TP1 on sheet Aux Power Supply
U3 = UCD3138128PFC: UCD3138128PFC, PFC0080; Alternate Manufacturer: None; Manufacturer: Texas Instruments; SymbolCreator: a0411947; CompType: IC; U/M: EA
U19 = SN65HVD233D: 3.3V CAN Transceiver with Standby Mode, Loop-back, 6 mA, -40 to 125 degC, 8-pin SOIC (D), Green (RoHS & no Sb/Br); Manufacturer: Texas Instruments; Alternate PartNumber: Equivalent; Drivers Per Package: 1; Bus Fault Voltage(V): +/-30; Transient Pulse Protection(V): -100 to 100; ICC(Max)(mA): 6; Supply Voltage(s)(V): 3.3; Rating: Catalog

## Sheet bidirectional-phase1.SchDoc: Phase 1
size 431 x 279 mm; Date: Not shown in title block; ApprovedBy: Not shown in title block; CheckedBy: Not shown in title block; Author: Not shown in title block; CompanyName: Not shown in title block; Engineer: Not shown in title block; Organization: Not shown in title block; Address1: Not shown in title block; Address2: Not shown in title block; Address3: Not shown in title block; Address4: Not shown in title block; DocumentNumber: 4; Revision: Use project parameter SCH_Rev; SheetNumber: 4; SheetTotal: 6; PageSetup: Record=PageOptions|CenterHorizontal=True|CenterVertical=True|PrintScale=0.96|XCorrection=1.00|YCorrection=1.00|PrintKind=0|BorderSize=5000000|LeftOffset=0|BottomOffset=0|Orientation=2|PaperLength=1000|PaperWidth=1000|Scale=100|PaperSource=15|PrintQuality=600|MediaType=1|DitherType=10|PaperKind=11x17|PrintScaleMode=1
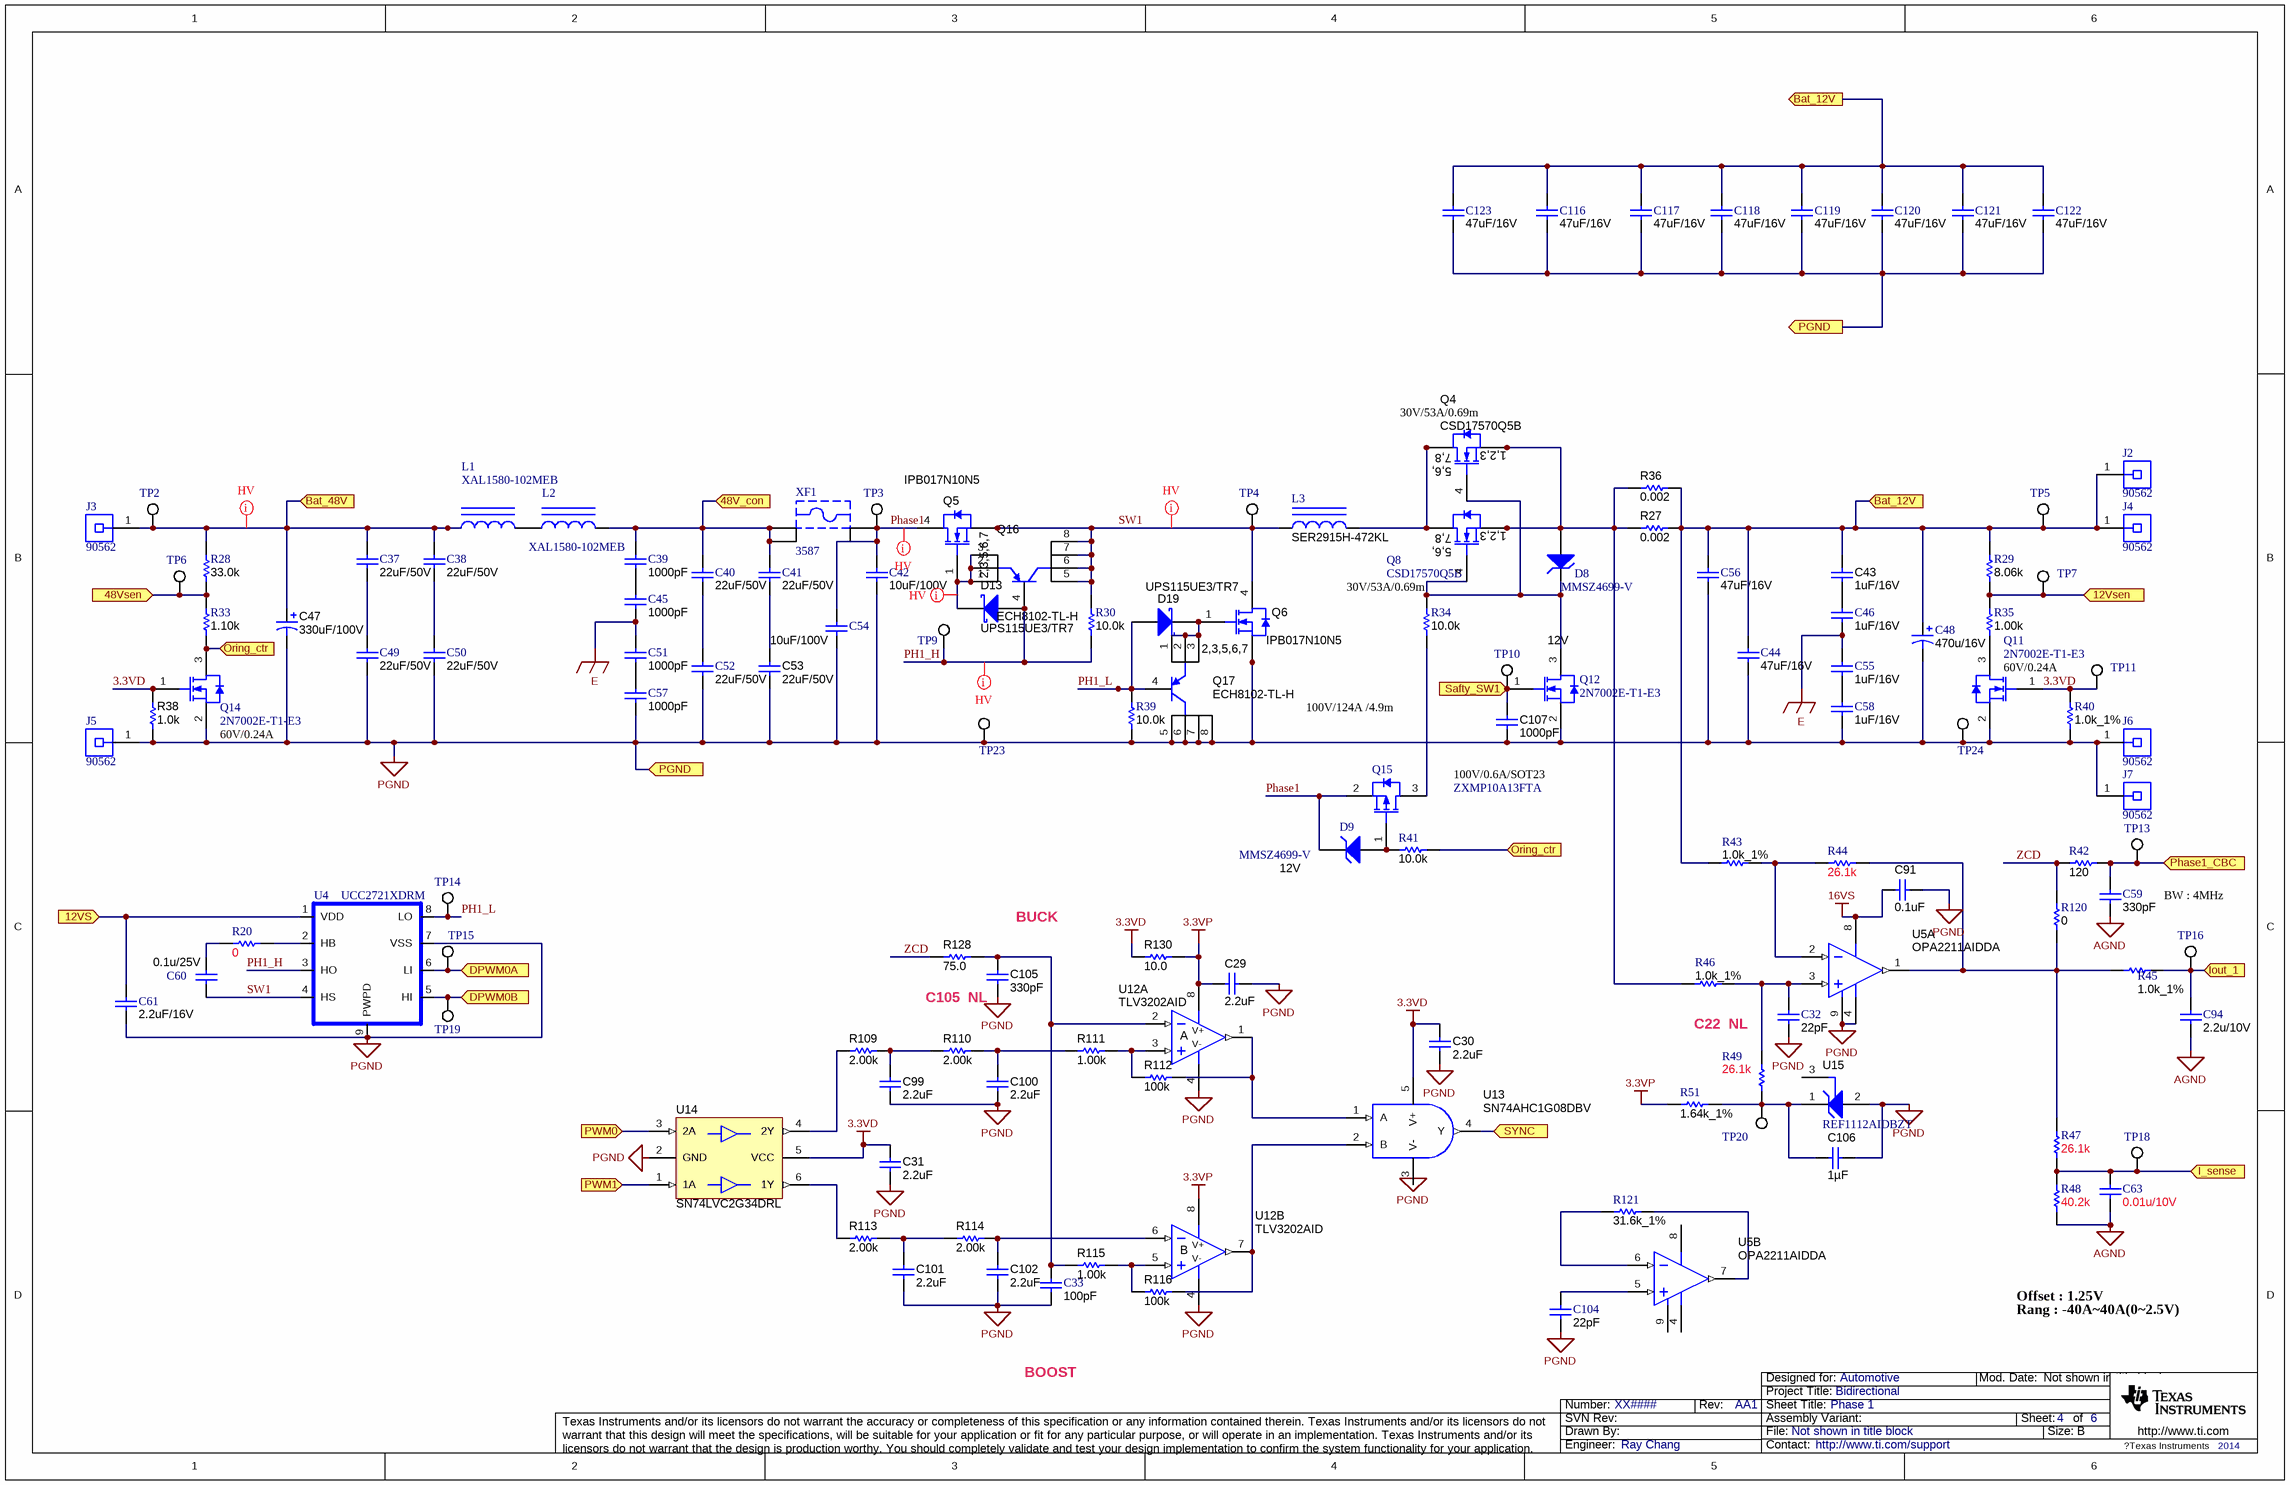
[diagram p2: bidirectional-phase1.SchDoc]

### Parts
(Parts that share a designator on the sheet are numbered #1, #2 ... from top to bottom, then left to right.)
C29  ValueDisplayed: 2.2uF  [0603]  (hidden comment: C0603C225K9PACTU)
C30  ValueDisplayed: 2.2uF  [0603]  (hidden comment: C0603C225K9PACTU)
C31  ValueDisplayed: 2.2uF  [0603]  (hidden comment: C0603C225K9PACTU)
C32  ValueDisplayed: 22pF  [0603]  (hidden comment: 06035A220JAT2A)
C33  ValueDisplayed: 100pF  [0603]  (hidden comment: 06033C101KAT2A)
C37  ValueDisplayed: 22uF/50V  [CKG57N]  (hidden comment: CKG57NX5R1H226M500JH)
C38  ValueDisplayed: 22uF/50V  [CKG57N]  (hidden comment: CKG57NX5R1H226M500JH)
C39#2  ValueDisplayed: 1000pF  [0603]  (hidden comment: 06031C102JAT2A)
C40  ValueDisplayed: 22uF/50V  [CKG57N]  (hidden comment: CKG57NX5R1H226M500JH)
C41  ValueDisplayed: 22uF/50V  [CKG57N]  (hidden comment: CKG57NX5R1H226M500JH)
C42  ValueDisplayed: 10uF/100V  [2220]  (hidden comment: C5750X7S2A106M)
C43  ValueDisplayed: 1uF/16V  [0805_HV]  (hidden comment: B37941K9105K62)
C44  ValueDisplayed: 47uF/16V  [1210]  (hidden comment: GRM32ER61C476ME15L)
C45  ValueDisplayed: 1000pF  [0603]  (hidden comment: 06031C102JAT2A)
C46  ValueDisplayed: 1uF/16V  [0805_HV]  (hidden comment: B37941K9105K62)
C47  ValueDisplayed: 330uF/100V  [CAPSMT_62_MN0]  (hidden comment: EMVE101GTR331MMN0S)
C48  ValueDisplayed: 470u/16V  [CAPSMT_62_JA0]  (hidden comment: EMVA250ADA471MJA0G)
C49  ValueDisplayed: 22uF/50V  [CKG57N]  (hidden comment: CKG57NX5R1H226M500JH)
C50  ValueDisplayed: 22uF/50V  [CKG57N]  (hidden comment: CKG57NX5R1H226M500JH)
C51  ValueDisplayed: 1000pF  [0603]  (hidden comment: 06031C102JAT2A)
C52  ValueDisplayed: 22uF/50V  [CKG57N]  (hidden comment: CKG57NX5R1H226M500JH)
C53  ValueDisplayed: 22uF/50V  [CKG57N]  (hidden comment: CKG57NX5R1H226M500JH)
C54  ValueDisplayed: 10uF/100V  [2220]  (hidden comment: C5750X7S2A106M)
C55  ValueDisplayed: 1uF/16V  [0805_HV]  (hidden comment: B37941K9105K62)
C56  ValueDisplayed: 47uF/16V  [1210]  (hidden comment: GRM32ER61C476ME15L)
C57  ValueDisplayed: 1000pF  [0603]  (hidden comment: 06031C102JAT2A)
C58  ValueDisplayed: 1uF/16V  [0805_HV]  (hidden comment: B37941K9105K62)
C59  ValueDisplayed: 330pF  [0603]  (hidden comment: 06035A331JAT2A)
C60  ValueDisplayed: 0.1u/25V  [0603]  (hidden comment: 06033C104KAT2A)
C61  ValueDisplayed: 2.2uF/16V  [0805_HV]  (hidden comment: 0805YD225KAT2A)
C63  ValueDisplayed: 0.01u/10V  [0603]  (hidden comment: 06031C103JAT2A)
C91  ValueDisplayed: 0.1uF  [0603]  (hidden comment: 06033C104JAT2A)
C94  ValueDisplayed: 2.2u/10V  [0603]  (hidden comment: C0603C225K8PACTU)
C99  ValueDisplayed: 2.2uF  [0805_HV]  (hidden comment: 0805YD225KAT2A)
C100  ValueDisplayed: 2.2uF  [0805_HV]  (hidden comment: 0805YD225KAT2A)
C101  ValueDisplayed: 2.2uF  [0805_HV]  (hidden comment: 0805YD225KAT2A)
C102  ValueDisplayed: 2.2uF  [0805_HV]  (hidden comment: 0805YD225KAT2A)
C104  ValueDisplayed: 22pF  [0603]  (hidden comment: 06035A220JAT2A)
C105  ValueDisplayed: 330pF  [0603]  (hidden comment: 06031C331JAT2A)
C106  ValueDisplayed: 1µF  [0603_095]  (hidden comment: C0603C105K3RACTU)
C107  ValueDisplayed: 1000pF  [0603]  (hidden comment: C0603X102K5RACTU)
C116  ValueDisplayed: 47uF/16V  [1210]  (hidden comment: GRM32ER61C476ME15L)
C117  ValueDisplayed: 47uF/16V  [1210]  (hidden comment: GRM32ER61C476ME15L)
C118  ValueDisplayed: 47uF/16V  [1210]  (hidden comment: GRM32ER61C476ME15L)
C119  ValueDisplayed: 47uF/16V  [1210]  (hidden comment: GRM32ER61C476ME15L)
C120  ValueDisplayed: 47uF/16V  [1210]  (hidden comment: GRM32ER61C476ME15L)
C121  ValueDisplayed: 47uF/16V  [1210]  (hidden comment: GRM32ER61C476ME15L)
C122  ValueDisplayed: 47uF/16V  [1210]  (hidden comment: GRM32ER61C476ME15L)
C123  ValueDisplayed: 47uF/16V  [1210]  (hidden comment: GRM32ER61C476ME15L)
D8  MMSZ4699-V  value 12V  [SOD-123]
D9  MMSZ4699-V  value 12V  [SOD-123]
D13  UPS115UE3/TR7  [DO-216AA]
D19  UPS115UE3/TR7  [DO-216AA]
J2  90562  [Morris_90562]
J3  90562  [Morris_90562]
J4  90562  [Morris_90562]
J5  90562  [Morris_90562]
J6  90562  [Morris_90562]
J7  90562  [Morris_90562]
L1  XAL1580-102MEB  [XAL1580]
L2  XAL1580-102MEB  [XAL1580]
L3  SER2915H-472KL  [SER2915H]
Q4  CSD17570Q5B  [TRANS_NexFET_Q5B]
Q5  IPB017N10N5  [DDPAK-7]
Q6  IPB017N10N5  [DDPAK-7]
Q8  CSD17570Q5B  [TRANS_NexFET_Q5B]
Q11  2N7002E-T1-E3  [SOT-23]
Q12  2N7002E-T1-E3  [SOT-23]
Q14  2N7002E-T1-E3  [SOT-23]
Q15  ZXMP10A13FTA  [SOT-23]
Q16  ECH8102-TL-H  [ECH8]
Q17  ECH8102-TL-H  [ECH8]
R20  value 0  [0603]  (hidden comment: MCR03EZPJ000)
R27  ValueDisplayed: 0.002  [2512]  (hidden comment: ERJ-M1WTF2M0U)
R28  ValueDisplayed: 33.0k  [0603]  (hidden comment: CRCW060333K0FKEA)
R29  ValueDisplayed: 8.06k  [0603]  (hidden comment: CRCW06038K06FKEA)
R30  value 10.0k  [0603]  (hidden comment: RG1608P-103-B-T5)
R33  ValueDisplayed: 1.10k  [0603]  (hidden comment: RC0603FR-071K1L)
R34  ValueDisplayed: 10.0k  [0603]  (hidden comment: CRCW060310K0FKEA)
R35  ValueDisplayed: 1.00k  [0603]  (hidden comment: CRCW06031K00FKEA)
R36  ValueDisplayed: 0.002  [2512]  (hidden comment: ERJ-M1WTF2M0U)
R38  value 1.0k  [0603]  (hidden comment: CRCW06031K00JNEA)
R39  value 10.0k  [0603]  (hidden comment: RG1608P-103-B-T5)
R40  value 1.0k_1%  [0603]  (hidden comment: CRCW06031K00JNEA)
R41  ValueDisplayed: 10.0k  [0603]  (hidden comment: CRCW060310K0FKEA)
R42  ValueDisplayed: 120  [0603]  (hidden comment: CRCW0603120RJNEA)
R43#2  value 1.0k_1%  [0603]  (hidden comment: CRCW06031K00JNEA)
R44  value 26.1k  [0603]  (hidden comment: CRCW060326K1FKEA)
R45  value 1.0k_1%  [0603]  (hidden comment: CRCW06031K00JNEA)
R46  value 1.0k_1%  [0603]  (hidden comment: CRCW06031K00JNEA)
R47  value 26.1k  [0603]  (hidden comment: CRCW060326K1FKEA)
R48  value 40.2k  [0603]  (hidden comment: CRCW060340K2FKEA)
R49  value 26.1k  [0603]  (hidden comment: CRCW060326K1FKEA)
R51  value 1.64k_1%  [0603]  (hidden comment: CRCW06031K65FKEA)
R109  value 2.00k  [0603]  (hidden comment: CRCW06032K00FKEA)
R110  value 2.00k  [0603]  (hidden comment: CRCW06032K00FKEA)
R111  value 1.00k  [0603]  (hidden comment: CRCW06031K00FKEA)
R112  ValueDisplayed: 100k  [0603]  (hidden comment: CRCW0603100KJNEA)
R113  value 2.00k  [0603]  (hidden comment: CRCW06032K00FKEA)
R114  value 2.00k  [0603]  (hidden comment: CRCW06032K00FKEA)
R115  value 1.00k  [0603]  (hidden comment: CRCW06031K00FKEA)
R116  ValueDisplayed: 100k  [0603]  (hidden comment: CRCW0603100KJNEA)
R120  value 0  [0603]  (hidden comment: ERJ-3GEY0R00V)
R121  value 31.6k_1%  [0603]  (hidden comment: CRCW060331K6FKEA)
R128  ValueDisplayed: 75.0  [0603]  (hidden comment: CRCW060375R0FKEA)
R130  value 10.0  [0603]  (hidden comment: CRCW060310R0FKEA)
TP2  5002  [Keystone5002]  (value not drawn)
TP3  5016  [Testpoint_Keystone_Compact]  (value not drawn)
TP4  5002  [Keystone5002]  (value not drawn)
TP5  5002  [Keystone5002]  (value not drawn)
TP6  5002  [Keystone5002]  (value not drawn)
TP7  5002  [Keystone5002]  (value not drawn)
TP9  5002  [Keystone5002]  (value not drawn)
TP10  5002  [Keystone5002]  (value not drawn)
TP11  5002  [Keystone5002]  (value not drawn)
TP13  5002  [Keystone5002]  (value not drawn)
TP14  5002  [Keystone5002]  (value not drawn)
TP15  5002  [Keystone5002]  (value not drawn)
TP16  5002  [Keystone5002]  (value not drawn)
TP18  5002  [Keystone5002]  (value not drawn)
TP19  5002  [Keystone5002]  (value not drawn)
TP20  5002  [Keystone5002]  (value not drawn)
TP23  5002  [Keystone5002]  (value not drawn)
TP24  5002  [Keystone5002]  (value not drawn)
U4  UCC2721XDRM  [DRM0008A]
U5  OPA2211AIDDA  [DDA0008C_N]  (parts A,B of 2)
U12  TLV3202AID  [D0008A_L]  (parts A,B of 2)
U13  SN74AHC1G08DBV  [DBV0005A_N]
U14  SN74LVC2G34DRL  [DRL0006A_N]
U15  REF1112AIDBZT  [DBZ0003A_N]
XF1  3587  [KEYSTONE_3587]

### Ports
12VS, 12Vsen, 48V_con, 48Vsen, Bat_12V, Bat_48V, DPWM0A, DPWM0B, I_sense, Iout_1, Oring_ctr, PGND, Phase1_CBC, PWM0, PWM1, Safty_SW1, SYNC

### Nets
3.3VD: C30.1 C31.2 Q11.1(G) Q14.1(G) R38.2 R40.2 R130.2 TP11.1 U13.5(V+) U14.5(VCC)
3.3VP: C29.2 R51.1 R130.1 U12.8(V+)
16VS: C91.1 U5.8(V+)
AGND: C59.2 C63.2 C94.2 R48.1
E: C45.2 C46.2 C51.1 C55.1
PGND: C29.1 C30.2 C31.1 C32.2 C33.2 C42.2 C44.2 C47.2(-) C48.2(-) C49.2 C50.2 C52.2 C53.2 C54.2 C56.2 C57.2 C58.2 C61.2 C91.2 C99.2 C100.2 C101.2 C102.2 C104.2 C105.2 C106.1 C107.2 C116.2 C117.2 C118.2 C119.2 C120.2 C121.2 C122.2 C123.2 J5.1 J6.1 J7.1 Q6.2(S) Q6.3(S) Q6.5(S) Q6.6(S) Q6.7(S) Q11.2(S) Q12.2(S) Q14.2(S) Q17.5(C) Q17.6(C) Q17.7(C) Q17.8(C) R38.1 R39.1 R40.1 TP23.1 TP24.1 U4.7(VSS) U4.9(PWPD) U5.4(V-) U5.9(EP) U12.4(V-) U14.2(GND) U15.2(GND) ; port PGND
12VS: C61.1 U4.1(VDD) ; port 12VS
12Vsen: R29.1 R35.2 TP7.1 ; port 12Vsen
48V_con: C39#2.1 C40.1 C41.1 L2.2 XF1.1 XF1.2 ; port 48V_con
48Vsen: R28.1 R33.2 TP6.1 ; port 48Vsen
Bat_12V: C43.1 C44.1 C48.1(+) C56.1 C116.1 C117.1 C118.1 C119.1 C120.1 C121.1 C122.1 C123.1 J2.1 J4.1 R27.2 R29.2 R36.2 R43#2.1 TP5.1 ; port Bat_12V
Bat_48V: C37.1 C38.1 C47.1(+) J3.1 L1.1 R28.2 TP2.1 ; port Bat_48V
DPWM0A: TP15.1 U4.6(LI) ; port DPWM0A
DPWM0B: TP19.1 U4.5(HI) ; port DPWM0B
I_sense: C63.1 R47.1 R48.2 TP18.1 ; port I_sense
Iout_1: C94.1 R45.2 TP16.1 ; port Iout_1
Oring_ctr: Q14.3(D) R33.1 R41.1 ; port Oring_ctr
PH1_H: D13.2(A) Q16.4(B) R30.1 TP9.1 U4.3(HO)
PH1_L: D19.2(A) Q17.4(B) R39.2 TP14.1 U4.8(LO)
Phase1: C42.1 C54.1 D9.1(K) Q5.4(D) Q15.2(S) TP3.1 XF1.3 XF1.4
Phase1_CBC: C59.1 R42.2 TP13.1 ; port Phase1_CBC
PWM0: U14.3(2A) ; port PWM0
PWM1: U14.1(1A) ; port PWM1
Safty_SW1: C107.1 Q12.1(G) TP10.1 ; port Safty_SW1
SW1: C60.2 L3.1 Q5.2(S) Q5.3(S) Q5.5(S) Q5.6(S) Q5.7(S) Q6.4(D) Q16.5(C) Q16.6(C) Q16.7(C) Q16.8(C) R30.2 TP4.1 U4.4(HS)
SYNC: U13.4(Y) ; port SYNC
ZCD: R42.1 R120.2 R128.1
NetC32_1: C32.1 R46.2 R49.2 U5.3(IN_A+)
NetC33_1: C33.1 C105.1 R115.1 R128.2 U12.2(IN-)
NetC37_2: C37.2 C49.1
NetC38_2: C38.2 C50.1
NetC39#2_2: C39#2.2 C45.1
NetC40_2: C40.2 C52.1
NetC41_2: C41.2 C53.1
NetC43_2: C43.2 C46.1
NetC51_2: C51.2 C57.1
NetC55_2: C55.2 C58.1
NetC60_1: C60.1 R20.1
NetC99_1: C99.1 R109.2 R110.1
NetC100_1: C100.1 R110.2 R111.1
NetC101_1: C101.1 R113.2 R114.1
NetC102_1: C102.1 R114.2 U12.6(IN-)
NetC104_1: C104.1 U5.5(IN_B+)
NetC106_2: C106.2 R49.1 R51.2 TP20.1 U15.1(VO)
NetD8_1: D8.1(K) Q4.4(G) Q8.4(G) Q12.3(D) R34.2
NetD8_2: D8.2(A) Q4.1(S) Q4.2(S) Q4.3(S) Q8.1(S) Q8.2(S) Q8.3(S) R27.1 R36.1 R46.1
NetD9_2: D9.2(A) Q15.1(G) R41.2
NetD13_1: D13.1(K) Q5.1(G) Q16.1(E) Q16.2(E) Q16.3(E)
NetD19_1: D19.1(K) Q6.1(G) Q17.1(E) Q17.2(E) Q17.3(E)
NetL1_2: L1.2 L2.1
NetL3_2: L3.2 Q4.5(D) Q4.6(D) Q4.7(D) Q4.8(D) Q8.5(D) Q8.6(D) Q8.7(D) Q8.8(D)
NetQ11_3: Q11.3(D) R35.1
NetQ15_3: Q15.3(D) R34.1
NetR20_2: R20.2 U4.2(HB)
NetR43#2_2: R43#2.2 R44.1 U5.2(IN_A-)
NetR44_2: R44.2 R45.1 R47.2 R120.1 U5.1(OUT_A)
NetR109_1: R109.1 U14.4(2Y)
NetR111_2: R111.2 R112.2 U12.3(IN+)
NetR112_1: R112.1 U12.1(OUT) U13.1(A)
NetR113_1: R113.1 U14.6(1Y)
NetR115_2: R115.2 R116.2 U12.5(IN+)
NetR116_1: R116.1 U12.7(OUT) U13.2(B)
NetR121_1: R121.1 U5.6(IN_B-)
NetR121_2: R121.2 U5.7(OUT_B)

Not connected (* = marked no-connect by the designer): U13 3(V-); U15 3(NC)

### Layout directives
net class HV: Bat_48V, NetD13_1, PH1_H, Phase1, SW1

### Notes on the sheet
- (near Q4) 30V/53A/0.69m
- (near R34) 30V/53A/0.69m
- (near Q11) 60V/0.24A
- (near Q14) 60V/0.24A
- 100V/124A /4.9m
- 100V/0.6A/SOT23
- BW : 4MHz
- BUCK
- (near C105) C105  NL
- C22  NL
- Offset : 1.25V
- BOOST
- Rang : -40A~40A(0|.5V)
- Labels drawn without touching a wire or pin: PGND

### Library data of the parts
C29-C31 = C0603C225K9PACTU: CAP, CERM, 2.2uF, 6.3V, +/-10%, X5R, 0603; Manufacturer: Kemet; Polarized: N; CompType: Capacitor; U/M: EA; Cap_F: 0.0000022; Tolerance_%: 10; Value1: Unknown; VDC_V: 6.3; TaMin_C: -55; TaMax_C: 85
C32 C104 = 06035A220JAT2A: CAP, CERM, 22pF, 50V, +/-5%, C0G/NP0, 0603; Manufacturer: AVX; Polarized: N; CompType: Capacitor; U/M: EA; Cap_F: 0.000000000022; Tolerance_%: 5; ESR_Ohm: 0.259; Value1: 0.259 ohm; VDC_V: 50; TaMin_C: -55; TaMax_C: 125
C33 = 06033C101KAT2A: CAP, CERM, 100pF, 25V, +/-10%, X7R, 0603; Manufacturer: AVX; Polarized: N; CompType: Capacitor; U/M: EA; Cap_F: 0.0000000001; Tolerance_%: 10; Value1: Unknown; VDC_V: 25; TaMin_C: -55; TaMax_C: 125
C37 C38 C40 C41 C49 C50 C52 C53 = CKG57NX5R1H226M500JH: CAP, CERM, 22uF, 50V, +/-20%, X5R, 6x5x5mm; Manufacturer: TDK; Polarized: N; CompType: Capacitor; U/M: EA; Cap_F: 0.000022; Tolerance_%: 20; Value1: Unknown; VDC_V: 50; TaMin_C: -55; TaMax_C: 85; Cap_Case: 2220
C39#2 C45 C51 C57 = 06031C102JAT2A: CAP, CERM, 1000pF, 100V, +/-5%, X7R, 0603; Manufacturer: AVX; Polarized: N; CompType: Capacitor; U/M: EA; Cap_F: 0.000000001; Tolerance_%: 5; ESR_Ohm: 0.276; Value1: 0.276 ohm; VDC_V: 100; TaMin_C: -55; TaMax_C: 125
C42 C54 = C5750X7S2A106M: CAP, CERM, 10uF, 100V, +/-20%, X7S, 2220; Manufacturer: TDK; Polarized: N; CompType: Capacitor; U/M: EA; Cap_F: 0.00001; Tolerance_%: 20; ESR_Ohm: 0.005; Value1: 0.005 ohm; VDC_V: 100; IRMS_A: 6.45; TaMin_C: -55; TaMax_C: 125
C43 C46 C55 C58 = B37941K9105K62: CAP, CERM, 1uF, 16V, +/-10%, X7R, 0805; Manufacturer: EPCOS Inc; Polarized: N; CompType: Capacitor; U/M: EA; Cap_F: 0.000001; Tolerance_%: 10; Value1: Unknown; VDC_V: 16; TaMin_C: -55; TaMax_C: 125; Cap_Case: 0805
C44 C56 C116-C123 = GRM32ER61C476ME15L: CAP, CERM, 47uF, 16V, +/-20%, X5R, 1210; Manufacturer: MuRata; Polarized: N; CompType: Capacitor; U/M: EA; Cap_F: 0.000047; Tolerance_%: 20; ESR_Ohm: 0.002; Value1: 0.002 ohm; VDC_V: 16; TaMin_C: -55; TaMax_C: 85
C47 = EMVE101GTR331MMN0S: CAP, AL, 330uF, 100V, +/-20%,  ohm, SMD; Manufacturer: Nippon Chemi-Con; Polarized: Y; CompType: Capacitor; U/M: EA; Cap_F: 0.00033; Tolerance_%: 20; Value1: Unknown; VDC_V: 100; IRMS_A: 0.98; TaMin_C: -40; TaMax_C: 105; Cap_Case: MN0
C48 = EMVA250ADA471MJA0G: CAP, AL, 470uF, 25V, +/-20%,  ohm, SMD; Manufacturer: Nippon Chemi-Con; Polarized: Y; CompType: Capacitor; U/M: EA; Cap_F: 0.00047; Tolerance_%: 20; Value1: Unknown; VDC_V: 25; IRMS_A: 0.4; TaMin_C: -40; TaMax_C: 85; Cap_Case: JA0
C59 = 06035A331JAT2A: CAP, CERM, 330pF, 50V, +/-5%, C0G/NP0, 0603; Manufacturer: AVX; Polarized: N; CompType: Capacitor; U/M: EA; Cap_F: 0.00000000033; Tolerance_%: 5; ESR_Ohm: 0.071; Value1: 0.071 ohm; VDC_V: 50; TaMin_C: -55; TaMax_C: 125
C60 = 06033C104KAT2A: CAP, CERM, 0.1uF, 25V, +/-10%, X7R, 0603; Manufacturer: AVX; Polarized: N; CompType: Capacitor; U/M: EA; Cap_F: 0.0000001; Tolerance_%: 10; ESR_Ohm: 0.05; Value1: 0.05 ohm; VDC_V: 25; TaMin_C: -55; TaMax_C: 125
C61 C99-C102 = 0805YD225KAT2A: as C9 on sheet Aux Power Supply
C63 = 06031C103JAT2A: as C16 on sheet bidirectional-MCU
C91 = 06033C104JAT2A: as C4 on sheet Aux Power Supply
C94 = C0603C225K8PACTU: as C22 on sheet bidirectional-MCU
C105 = 06031C331JAT2A: CAP, CERM, 330pF, 100V, +/-5%, X7R, 0603; Manufacturer: AVX; Polarized: N; CompType: Capacitor; U/M: EA; Cap_F: 0.00000000033; Tolerance_%: 5; ESR_Ohm: 0.472; Value1: 0.472 ohm; VDC_V: 100; TaMin_C: -55; TaMax_C: 125
C106 = C0603C105K3RACTU: CAP, CERM, 1 µF, 25 V, +/- 10%, X7R, 0603_095; Manufacturer: Kemet; Polarized: N; CompType: Capacitor; Value: 1uF; U/M: EA; Cap_F: 0.000001; Tolerance_%: 10; Value1: Unknown; VDC_V: 25; Value2: 25V; TaMin_C: -55; TaMax_C: 125; Cap_Case: 0603
C107 = C0603X102K5RACTU: CAP, CERM, 1000 pF, 50 V, +/- 10%, X7R, 0603; Manufacturer: Kemet; Polarized: N; CompType: Capacitor; Value: 1000pF; U/M: EA; Cap_F: 0.000000001; Tolerance_%: 10; Value1: Unknown; VDC_V: 50; Value2: 50V; TaMin_C: -55; TaMax_C: 125
D8 D9 = MMSZ4699-V: Diode, Zener, 12V, 500mW, SOD-123; Manufacturer: Vishay-Semiconductor; SymbolCreator: a0412235; U/M: EA; Power_W: 0.5; Vz_V: 12; Value1: 0.5W; RJA_CperW: 67
D13 D19 = UPS115UE3/TR7: Diode, Schottky, 15 V, 1 A, DO-216-AA; Manufacturer: Microsemi; U/M: EA; Vf_V: 0.31; Value: 15V; Value1: 1A; Value2: 0.31V; Io_A: 1; Vr_V: 15; TJmax_C: 100
J2-J7 = 90562: Connector Lug, wire range #6 - 4/0, 600V; Manufacturer: Morris Products; SymbolCreator: a0799628; CompType: Receptacle; U/M: EA
L1 L2 = XAL1580-102MEB: Inductor, Shielded, Composite, 1uH, 57.5A, 0.000929 ohm, SMD; Manufacturer: Coilcraft; Ind_H: 1.0E-6; ValueDisplayed: 1µH; Imax_A: 57.5; Irms: 57.5A @ 40C rise; Isat: 73.5A @ 0.7% inductance drop; U/M: EA
L3 = SER2915H-472KL: Inductor, Shielded E Core, Ferrite, 4.7 µH, 30 A, 0.00186 ohm, SMD; Manufacturer: Coilcraft; Value: 4.7uH; Ind_H: 4.7E-6; ValueDisplayed: 4.7µH; Imax_A: 30; Irms: 30A @ 40C rise; Isat: 50.1A @ 30% inductance drop; Value2: 30A
Q4 Q8 = CSD17570Q5B: MOSFET, N-CH, 30V, 51A, SON 5x6mm; Manufacturer: Texas Instruments; Alternate Manufacturer: None; U/M: EA; ChType: N; VdsMax_V: 30; Value1: 0.0076 ohm; Rdson45_Ohm: 0.0076; Value2: 97 nC; QgTyp_nC: 97; Vgs_V: 20; IdsMax_A: 51
Q5 Q6 = IPB180N08S402ATMA1: MOSFET, N-CH, 80 V, 180 A, DDPAK-7; Manufacturer: Infineon Technologies; Alternate Manufacturer: None; SymbolCreator: a0412235; U/M: EA; ChType: N; Value: 80V; VdsMax_V: 80; Value1: ? ohm; Value2: 128 nC; QgTyp_nC: 128; Vgs_V: 20; IdsMax_A: 180
Q11 Q12 Q14 = 2N7002E-T1-E3: as Q2 on sheet Aux Power Supply
Q15 = ZXMP10A13FTA: MOSFET, P-CH, -100V, -0.6A, SOT-23; Manufacturer: Diodes Inc.; Alternate Manufacturer: None; U/M: EA; ChType: P; VdsMax_V: -100; Value1: 1 ohm; Rdson45_Ohm: 1; Value2: 3.5 nC; QgTyp_nC: 3.5; Vgs_V: -4; IdsMax_A: -0.6
Q16 Q17 = ECH8102-TL-H, ON Semiconductor: Transistor, PNP, 30 V, 12 A, SMD-8; CompType: BJT; PNP: 1; NPN: 0; Vceo_V: 30; Vcesat1_V: 0.08; Value: 30 V; IcRated_A: 12; Value1: 12 A; HfeMax: 560; TaMin_C: -55; TaMax_C: 150; U/M: EA
R20 = MCR03EZPJ000: as R15 on sheet bidirectional-MCU
R27 R36 = ERJ-M1WTF2M0U: RES, 0.002, 1%, 1 W, 2512; Manufacturer: Panasonic; CompType: Resistor; Value: 0.002; Value_Code: 2L000; Tolerance_%: 1; Value2: 1W; TempCo: ppm/C; U/M: EA
R28 = CRCW060333K0FKEA: RES, 33.0 k, 1%, 0.1 W, 0603; Manufacturer: Vishay-Dale; CompType: Resistor; Value: 33.0k; Res_ohm: 33000; Value_Code: 33k0; Tolerance_%: 1; Power_W: 0.1; Value2: 0.1W; VDC_V: 75; TempCo: 100 ppm/C; U/M: EA
R29 = CRCW06038K06FKEA: RES, 8.06 k, 1%, 0.1 W, 0603; Manufacturer: Vishay-Dale; CompType: Resistor; Value: 8.06k; Res_ohm: 8060; Value_Code: 8k06; Tolerance_%: 1; Power_W: 0.1; Value2: 0.1W; VDC_V: 75; TempCo: 100 ppm/C; EIA_Code: E96; U/M: EA
R30 R39 = RG1608P-103-B-T5: RES, 10.0k ohm, 0.1%, 0.1W, 0603; Manufacturer: Susumu Co Ltd; CompType: Resistor; Res_ohm: 10000; Value_Code: 10k0; Tolerance_%: 0.1; VDC_V: 75; TempCo: 25 ppm/C; EIA_Code: E192; U/M: EA
R33 = RC0603FR-071K1L: RES, 1.10 k, 1%, 0.1 W, 0603; Manufacturer: Yageo America; CompType: Resistor; Value: 1.10k; Res_ohm: 1100; Value_Code: 1k10; Tolerance_%: 1; Power_W: 0.1; Value2: 0.1W; VDC_V: 150; TempCo: 200 ppm/C; EIA_Code: E96; U/M: EA
R34 R41 = CRCW060310K0FKEA: RES, 10.0 k, 1%, 0.1 W, 0603; Manufacturer: Vishay-Dale; CompType: Resistor; Value: 10.0k; Res_ohm: 10000; Value_Code: 10k0; Tolerance_%: 1; Power_W: 0.1; Value2: 0.1W; VDC_V: 75; TempCo: 100 ppm/C; EIA_Code: E96; U/M: EA
R35 = CRCW06031K00FKEA: RES, 1.00 k, 1%, 0.1 W, 0603; Manufacturer: Vishay-Dale; CompType: Resistor; Value: 1.00k; Res_ohm: 1000; Value_Code: 1k00; Tolerance_%: 1; Power_W: 0.1; Value2: 0.1W; VDC_V: 75; TempCo: 100 ppm/C; EIA_Code: E96; U/M: EA
R38 R40 R43#2 R45 R46 = CRCW06031K00JNEA: as R8 on sheet Aux Power Supply
R42 = CRCW0603120RJNEA: RES, 120, 5%, 0.1 W, 0603; Manufacturer: Vishay-Dale; CompType: Resistor; Value: 120; Value_Code: 120R; Tolerance_%: 5; Power_W: 0.1; Value2: 0.1W; VDC_V: 75; TempCo: 200 ppm/C; EIA_Code: E24; U/M: EA
R44 R47 R49 = CRCW060326K1FKEA: RES, 26.1k ohm, 1%, 0.1W, 0603; Manufacturer: Vishay-Dale; CompType: Resistor; Res_ohm: 26100; Value_Code: 26k1; Tolerance_%: 1; Power_W: 0.1; VDC_V: 75; TempCo: 100 ppm/C; EIA_Code: E96; U/M: EA
R48 = CRCW060340K2FKEA: RES, 40.2k ohm, 1%, 0.1W, 0603; Manufacturer: Vishay-Dale; CompType: Resistor; Res_ohm: 40200; Value_Code: 40k2; Tolerance_%: 1; Power_W: 0.1; VDC_V: 75; TempCo: 100 ppm/C; EIA_Code: E96; U/M: EA
R51 = CRCW06031K65FKEA: RES, 1.65k ohm, 1%, 0.1W, 0603; Manufacturer: Vishay-Dale; CompType: Resistor; Res_ohm: 1650; Value_Code: 1k65; Tolerance_%: 1; Power_W: 0.1; VDC_V: 75; TempCo: 100 ppm/C; EIA_Code: E96; U/M: EA
R109 R110 R113 R114 = CRCW06032K00FKEA: RES, 2.00k ohm, 1%, 0.1W, 0603; Manufacturer: Vishay-Dale; CompType: Resistor; Res_ohm: 2000; Value_Code: 2k00; Tolerance_%: 1; Power_W: 0.1; VDC_V: 75; TempCo: 100 ppm/C; EIA_Code: E96; U/M: EA
R111 R115 = CRCW06031K00FKEA: as R17 on sheet bidirectional-MCU
R112 R116 = CRCW0603100KJNEA: as R12 on sheet Aux Power Supply
R120 = ERJ-3GEY0R00V: RES, 0 ohm, 5%, 0.1W, 0603; Manufacturer: Panasonic; CompType: Resistor; Value_Code: 0000; Tolerance_%: 5; Power_W: 0.1; VDC_V: 50; TempCo: 600 ppm/C; EIA_Code: E24; U/M: EA
R121 = CRCW060331K6FKEA: RES, 31.6k ohm, 1%, 0.1W, 0603; Manufacturer: Vishay-Dale; CompType: Resistor; Res_ohm: 31600; Value_Code: 31k6; Tolerance_%: 1; Power_W: 0.1; VDC_V: 75; TempCo: 100 ppm/C; EIA_Code: E96; U/M: EA
R128 = CRCW060375R0FKEA: RES, 75.0, 1%, 0.1 W, 0603; Manufacturer: Vishay-Dale; CompType: Resistor; Value: 75.0; Res_ohm: 75; Value_Code: 75R0; Tolerance_%: 1; Power_W: 0.1; Value2: 0.1W; TempCo: 100 ppm/C; EIA_Code: E96; U/M: EA
R130 = CRCW060310R0FKEA: RES, 10.0 ohm, 1%, 0.1W, 0603; Manufacturer: Vishay-Dale; CompType: Resistor; Res_ohm: 10; Value_Code: 10R0; Tolerance_%: 1; Power_W: 0.1; VDC_V: 75; TempCo: 100 ppm/C; EIA_Code: E96; U/M: EA
TP2 TP4-TP7 TP9-TP11 TP13-TP16 TP18-TP20 TP23 TP24 = 5002: as TP1 on sheet Aux Power Supply
TP3 = 5016: Test Point, Compact, SMT; Manufacturer: Keystone; CompType: Test Point Loop; U/M: EA
U4 = UCC2721XDRM: IC, 120V Boot, 4A Peak, High Frequency High-Side Low-Side Driver; Manufacturer: TI; Alternate Manufacturer: None; Area: 41800
U5 = OPA2211AIDDA: 1.1 nV/rtHz Noise, Low Power, Precision Operational Amplifier, 4.5 to 36 V, -40 to 125 degC, 8-pin SOP (DDA0008C), Green (RoHS & no Sb/Br); Manufacturer: Texas Instruments; Alternate PartNumber: Equivalent; CMRR(Min)(dB): 114; GBW(Typ)(MHz): 45; IIB(Max)(pA): 175000; Iq per channel(Max)(mA): 4.5; Number of Channels: 2; Offset Drift(Typ)(uV/C): 0.35; Packing: TUBE; Rating: Catalog; Slew Rate(Typ)(V/us): 27; Sub Family: High Supply Voltage Amplifier (>=30V), Low Noise Amp (<=10nV/rtHz), Low Offset Voltage Amplifier (<=500uV), Precision Amplifier; Total Supply Voltage(Max)(+5V is 5, +/-5V is 10): 36; Vio (25C)(Max)(mV): 0.15
U12 = TLV3202AID: 40-ns, microPOWER, Push-Pull Output Comparators, D0008A; Alternate Manufacturer: None; Manufacturer: Texas Instruments; CompType: IC; U/M: EA
U13 = SN74AHC1G08DBV: Single 2-Input Positive-AND Gate, DBV0005A; Manufacturer: Texas Instruments; CompType: IC; U/M: EA
U14 = SN74LVC2G34DRL: DUAL BUFFER GATE, DRL0006A; Alternate Manufacturer: None; Manufacturer: Texas Instruments; SymbolCreator: a0411947; CompType: IC; U/M: EA
U15 = REF1112AIDBZT: 1 uA Shunt Voltage Reference, 1.25 V, 10 ppm / degC, 5 mA, -40 to 85 degC, 3-pin SOT-23 (DBZ), Green (RoHS & no Sb/Br); Manufacturer: Texas Instruments; Alternate PartNumber: Equivalent; Initial Accuracy @ 25/deg C(%): 0.2; Iout/Iz(Max)(mA): 5; Min Iz for Regulation(uA): 1.2; Rating: Catalog; Temp Coeff(Max)(ppm/ degree C): 50; Temp Coeff(Typ)(ppm/ degree C): 10; VO(V): 1.25
XF1 = 3587: FuseHolder; Manufacturer: Keystone; SymbolCreator: a0799628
